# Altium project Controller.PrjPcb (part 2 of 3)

## Sheet Drivers - 34P.SchDoc: DRIVERS (34P) - 60KW GM4 DAB CONTROL
size 431 x 279 mm; Date: 02/2025; DocumentNumber: CRD60DD12N-GMB-CONTROL; Revision: 2.0; SheetNumber: 4; SheetTotal: 12; SheetSize: B
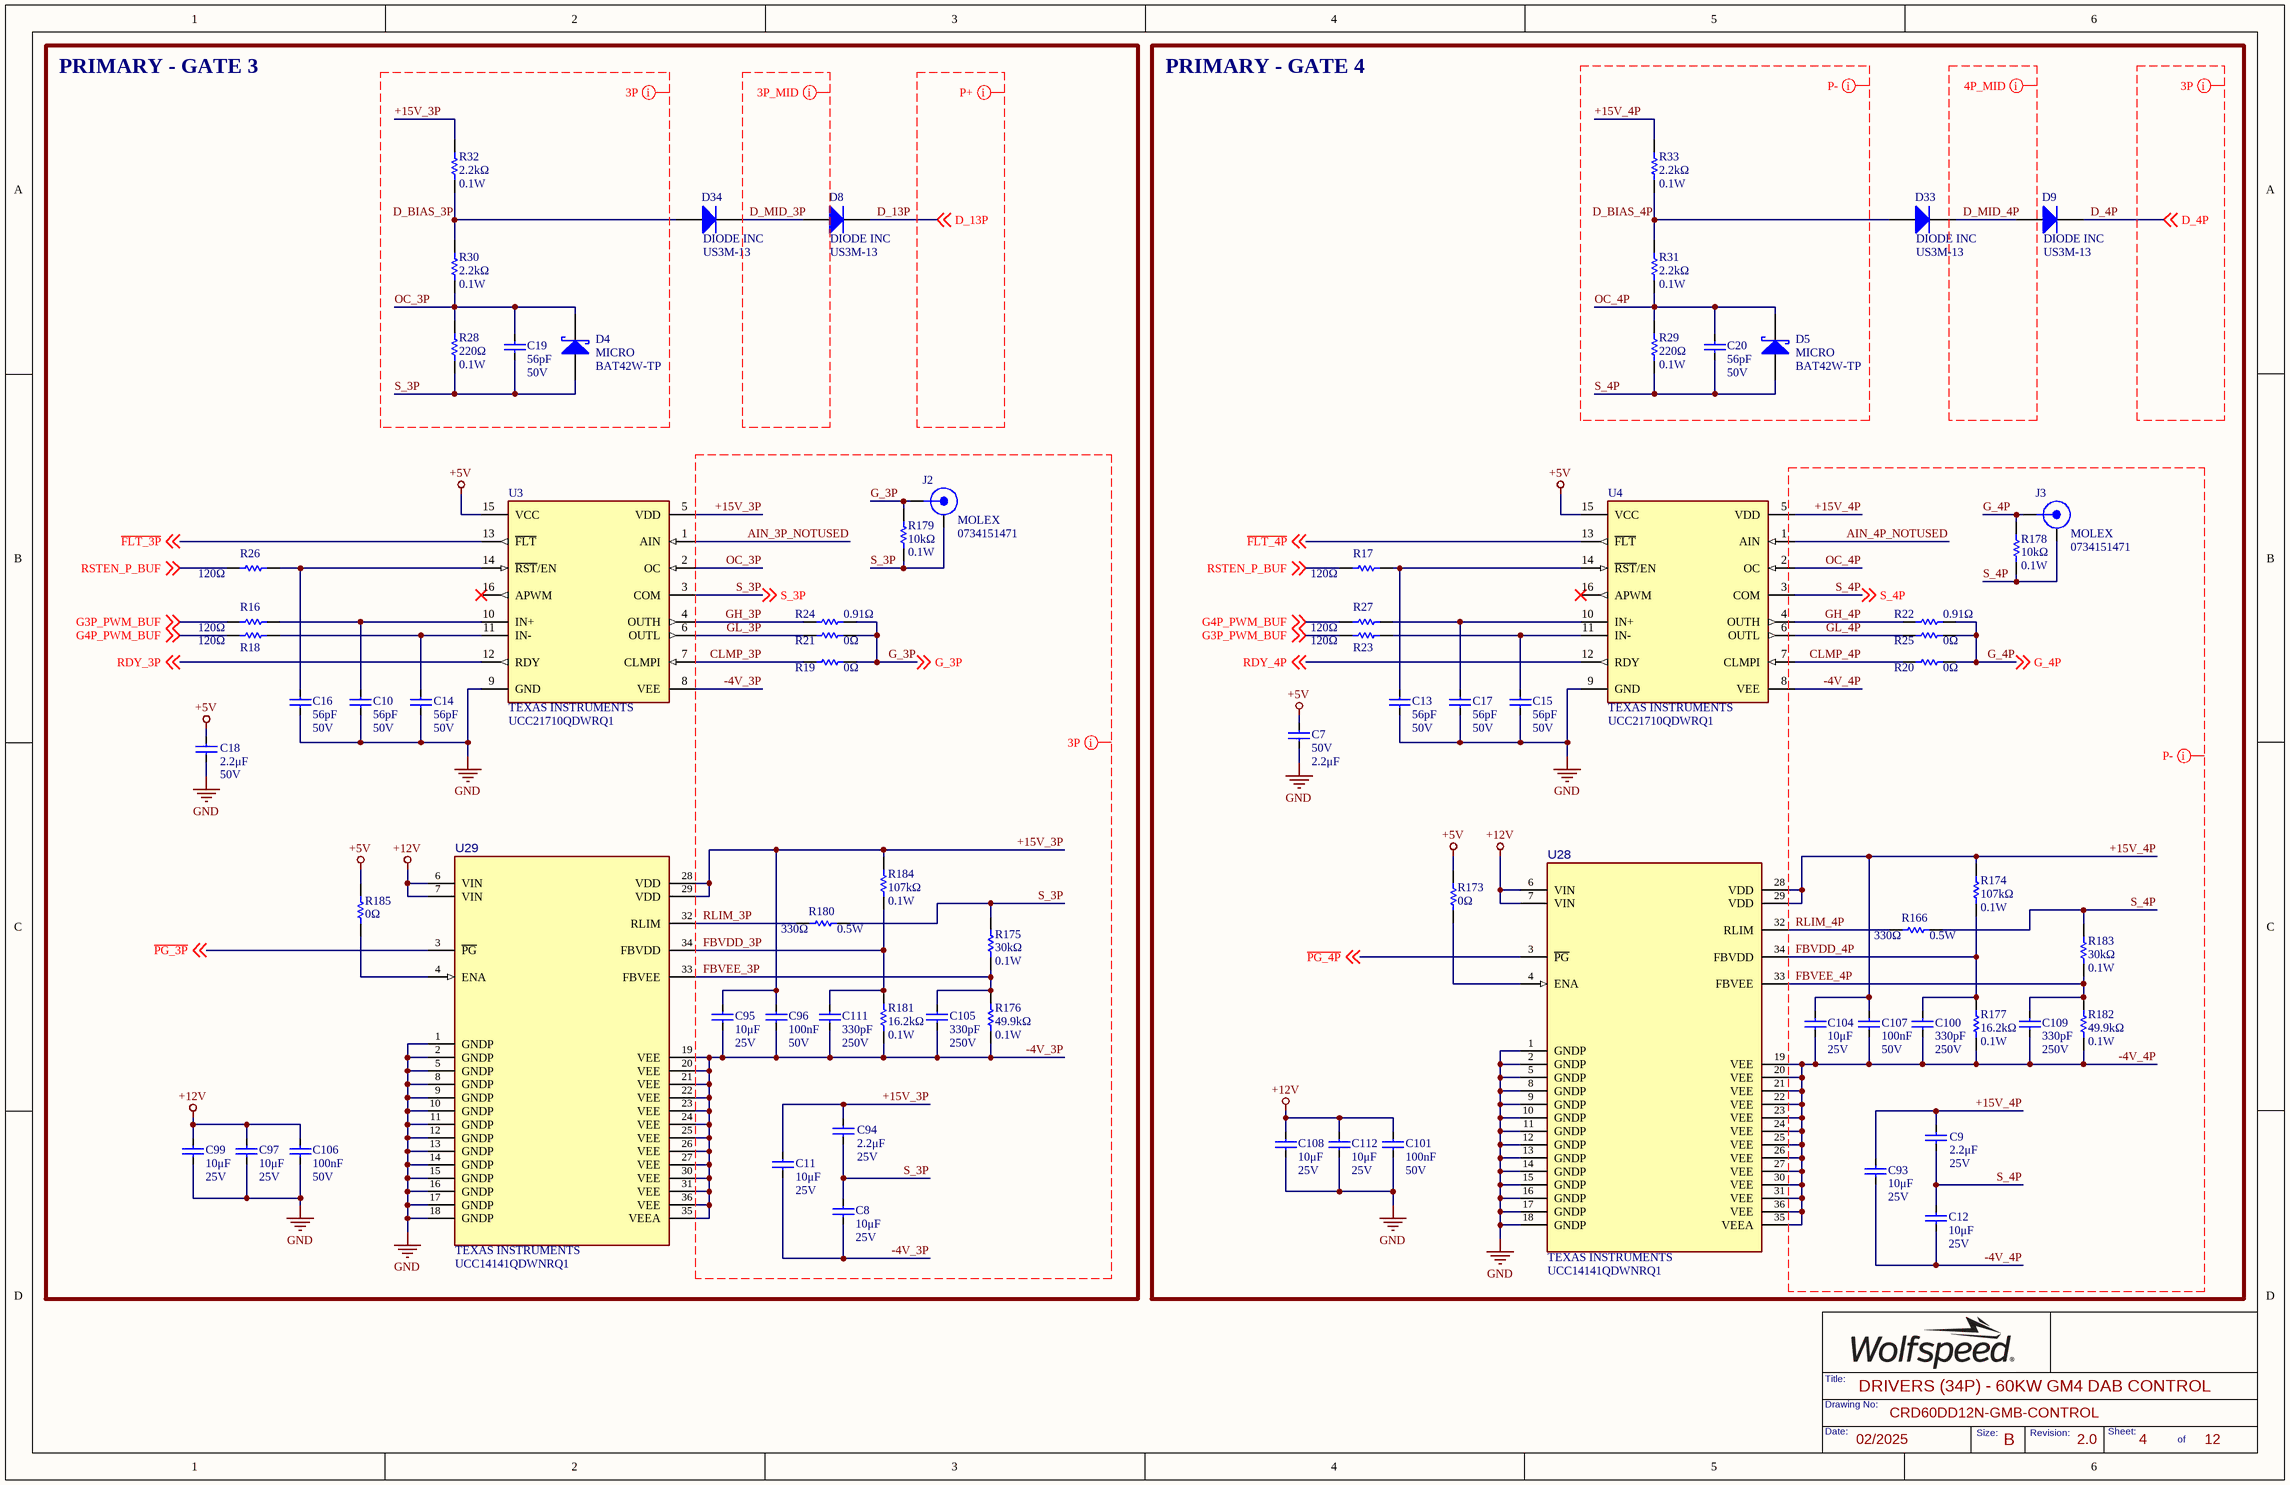
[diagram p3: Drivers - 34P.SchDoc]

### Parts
C7  Voltage Rating: 50V  Capacitance: 2.2μF  [FP-C0603C-CF-IPC_B]  (hidden comment: GRT188R61H225ME13D)
C8  value 10μF  Voltage Rating: 25V  [FP-CL31-IPC_C]  (hidden comment: CL31B106KAHSFNE)
C9  Voltage Rating: 25V  Capacitance: 2.2μF  [FP-CL31-IPC_C]  (hidden comment: 12063C225K4T2A)
C10  Capacitance: 56pF  Voltage Rating: 50V  [FP-C0603C-CF-IPC_B]  (hidden comment: CL10C560JB8NNNC)
C11  value 10μF  Voltage Rating: 25V  [FP-CL31-IPC_C]  (hidden comment: CL31B106KAHSFNE)
C12  value 10μF  Voltage Rating: 25V  [FP-CL31-IPC_C]  (hidden comment: CL31B106KAHSFNE)
C13  Capacitance: 56pF  Voltage Rating: 50V  [FP-C0603C-CF-IPC_B]  (hidden comment: CL10C560JB8NNNC)
C14  Capacitance: 56pF  Voltage Rating: 50V  [FP-C0603C-CF-IPC_B]  (hidden comment: CL10C560JB8NNNC)
C15  Capacitance: 56pF  Voltage Rating: 50V  [FP-C0603C-CF-IPC_B]  (hidden comment: CL10C560JB8NNNC)
C16  Capacitance: 56pF  Voltage Rating: 50V  [FP-C0603C-CF-IPC_B]  (hidden comment: CL10C560JB8NNNC)
C17  Capacitance: 56pF  Voltage Rating: 50V  [FP-C0603C-CF-IPC_B]  (hidden comment: CL10C560JB8NNNC)
C18  Voltage Rating: 50V  Capacitance: 2.2μF  [FP-C0603C-CF-IPC_B]  (hidden comment: GRT188R61H225ME13D)
C19  Capacitance: 56pF  Voltage Rating: 50V  [FP-C0603C-CF-IPC_B]  (hidden comment: CL10C560JB8NNNC)
C20  Capacitance: 56pF  Voltage Rating: 50V  [FP-C0603C-CF-IPC_B]  (hidden comment: CL10C560JB8NNNC)
C93  value 10μF  Voltage Rating: 25V  [FP-CL31-IPC_C]  (hidden comment: CL31B106KAHSFNE)
C94  Voltage Rating: 25V  Capacitance: 2.2μF  [FP-CL31-IPC_C]  (hidden comment: 12063C225K4T2A)
C95  value 10μF  Voltage Rating: 25V  [FP-CL31-IPC_C]  (hidden comment: CL31B106KAHSFNE)
C96  value 100nF  Voltage: 50V  [FP-C0603C-CF-IPC_B]  (hidden comment: CGA3E2X7R1H104K080AA)
C97  value 10μF  Voltage Rating: 25V  [FP-CL31-IPC_C]  (hidden comment: CL31B106KAHSFNE)
C99  value 10μF  Voltage Rating: 25V  [FP-CL31-IPC_C]  (hidden comment: CL31B106KAHSFNE)
C100  value 330pF  Voltage Rating: 250V  [FP-C0603C-CF-IPC_B]  (hidden comment: C0603C331JAGAC7867)
C101  value 100nF  Voltage: 50V  [FP-C0603C-CF-IPC_B]  (hidden comment: CGA3E2X7R1H104K080AA)
C104  value 10μF  Voltage Rating: 25V  [FP-CL31-IPC_C]  (hidden comment: CL31B106KAHSFNE)
C105  value 330pF  Voltage Rating: 250V  [FP-C0603C-CF-IPC_B]  (hidden comment: C0603C331JAGAC7867)
C106  value 100nF  Voltage: 50V  [FP-C0603C-CF-IPC_B]  (hidden comment: CGA3E2X7R1H104K080AA)
C107  value 100nF  Voltage: 50V  [FP-C0603C-CF-IPC_B]  (hidden comment: CGA3E2X7R1H104K080AA)
C108  value 10μF  Voltage Rating: 25V  [FP-CL31-IPC_C]  (hidden comment: CL31B106KAHSFNE)
C109  value 330pF  Voltage Rating: 250V  [FP-C0603C-CF-IPC_B]  (hidden comment: C0603C331JAGAC7867)
C111  value 330pF  Voltage Rating: 250V  [FP-C0603C-CF-IPC_B]  (hidden comment: C0603C331JAGAC7867)
C112  value 10μF  Voltage Rating: 25V  [FP-CL31-IPC_C]  (hidden comment: CL31B106KAHSFNE)
D4  Manufacturer: MICRO  [SOD3716X135N]  (hidden comment: BAT42W-TP)
D5  Manufacturer: MICRO  [SOD3716X135N]  (hidden comment: BAT42W-TP)
D8  Manufacturer: DIODE INC  [DIOM6959X25N]  (hidden comment: US3M-13)
D9  Manufacturer: DIODE INC  [DIOM6959X25N]  (hidden comment: US3M-13)
D33  Manufacturer: DIODE INC  [DIOM6959X25N]  (hidden comment: US3M-13)
D34  Manufacturer: DIODE INC  [DIOM6959X25N]  (hidden comment: US3M-13)
J2  0734151471  Manufacturer Print: MOLEX  [FP-73415-1471-MFG]
J3  0734151471  Manufacturer Print: MOLEX  [FP-73415-1471-MFG]
R16  value 120Ω  [FP-MCR03-IPC_B]  (hidden comment: RC0603JR-07120RL)
R17  value 120Ω  [FP-MCR03-IPC_B]  (hidden comment: RC0603JR-07120RL)
R18  value 120Ω  [FP-MCR03-IPC_B]  (hidden comment: RC0603JR-07120RL)
R19  Resistance: 0Ω  [FP-MCR03-IPC_B]  (hidden comment: CRCW06030000Z0EB)
R20  Resistance: 0Ω  [FP-MCR03-IPC_B]  (hidden comment: CRCW06030000Z0EB)
R21  value 0Ω  [RESC3125X70X40NL20T20]  (hidden comment: CRCW12100000Z0EAHP)
R22  value 0.91Ω  [RESC3125X70X40NL20T20]  (hidden comment: RCWE1210R910FKEA)
R23  value 120Ω  [FP-MCR03-IPC_B]  (hidden comment: RC0603JR-07120RL)
R24  value 0.91Ω  [RESC3125X70X40NL20T20]  (hidden comment: RCWE1210R910FKEA)
R25  value 0Ω  [RESC3125X70X40NL20T20]  (hidden comment: CRCW12100000Z0EAHP)
R26  value 120Ω  [FP-MCR03-IPC_B]  (hidden comment: RC0603JR-07120RL)
R27  value 120Ω  [FP-MCR03-IPC_B]  (hidden comment: RC0603JR-07120RL)
R28  Resistance: 220Ω  Power Rating: 0.1W  [FP-MCR03-IPC_B]  (hidden comment: RT0603FRE07220RL)
R29  Resistance: 220Ω  Power Rating: 0.1W  [FP-MCR03-IPC_B]  (hidden comment: RT0603FRE07220RL)
R30  value 2.2kΩ  Power: 0.1W  [FP-MCR03-IPC_B]  (hidden comment: RC0603FR-102K2L)
R31  value 2.2kΩ  Power: 0.1W  [FP-MCR03-IPC_B]  (hidden comment: RC0603FR-102K2L)
R32  value 2.2kΩ  Power: 0.1W  [FP-MCR03-IPC_B]  (hidden comment: RC0603FR-102K2L)
R33  value 2.2kΩ  Power: 0.1W  [FP-MCR03-IPC_B]  (hidden comment: RC0603FR-102K2L)
R166  value 330Ω  Power: 0.5W  [RESC3125X70X40NL20T20]  (hidden comment: RC1210JR-07330RL)
R173  Resistance: 0Ω  [FP-MCR03-IPC_B]  (hidden comment: CRCW06030000Z0EB)
R174  value 107kΩ  Power Rating: 0.1W  [FP-MCR03-IPC_B]  (hidden comment: RT0603BRD07107KL)
R175  value 30kΩ  Power Rating: 0.1W  [FP-MCR03-IPC_B]  (hidden comment: RT0603DRE0730KL)
R176  value 49.9kΩ  Power Rating: 0.1W  [FP-MCR03-IPC_B]  (hidden comment: RT0603FRE0749K9L)
R177  value 16.2kΩ  Power Rating: 0.1W  [FP-MCR03-IPC_B]  (hidden comment: RT0603BRD0716K2L)
R178  Resistance: 10kΩ  Max Power Dissipation: 0.1W  [FP-MCR03-IPC_B]  (hidden comment: ERJ3EKF1002V)
R179  Resistance: 10kΩ  Max Power Dissipation: 0.1W  [FP-MCR03-IPC_B]  (hidden comment: ERJ3EKF1002V)
R180  value 330Ω  Power: 0.5W  [RESC3125X70X40NL20T20]  (hidden comment: RC1210JR-07330RL)
R181  value 16.2kΩ  Power Rating: 0.1W  [FP-MCR03-IPC_B]  (hidden comment: RT0603BRD0716K2L)
R182  value 49.9kΩ  Power Rating: 0.1W  [FP-MCR03-IPC_B]  (hidden comment: RT0603FRE0749K9L)
R183  value 30kΩ  Power Rating: 0.1W  [FP-MCR03-IPC_B]  (hidden comment: RT0603DRE0730KL)
R184  value 107kΩ  Power Rating: 0.1W  [FP-MCR03-IPC_B]  (hidden comment: RT0603BRD07107KL)
R185  Resistance: 0Ω  [FP-MCR03-IPC_B]  (hidden comment: CRCW06030000Z0EB)
U3  UCC21710QDWRQ1  Manufacturer: TEXAS INSTRUMENTS  [FP-DW0016B-IPC_B]
U4  UCC21710QDWRQ1  Manufacturer: TEXAS INSTRUMENTS  [FP-DW0016B-IPC_B]
U28  Manufacturer: TEXAS INSTRUMENTS  [DWN0036-IPC-MFG]  (hidden comment: UCC14141QDWNRQ1)
U29  Manufacturer: TEXAS INSTRUMENTS  [DWN0036-IPC-MFG]  (hidden comment: UCC14141QDWNRQ1)

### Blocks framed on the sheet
PRIMARY - GATE 3: C8 C10 C11 C14 C16 C18 C19 C94-C97 C99 C105 C106 C111 D4 D8 D34 J2 R16 R18 R19 R21 R24 R26 R28 R30 R32 R175 R176 R179-R181 R184 R185 U3 U29
PRIMARY - GATE 4: C7 C9 C12 C13 C15 C17 C20 C93 C100 C101 C104 C107-C109 C112 D5 D9 D33 J3 R17 R20 R22 R23 R25 R27 R29 R31 R33 R166 R173 R174 R177 R178 R182 R183 U4 U28

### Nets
+5V: C7.1 C18.1 R173.2 R185.2 U3.15(VCC) U4.15(VCC)
+12V: C97.1 C99.1 C101.1 C106.1 C108.1 C112.1 U28.6(VIN) U28.7(VIN) U29.6(VIN) U29.7(VIN)
GND: C7.2 C10.2 C13.2 C14.2 C15.2 C16.2 C17.2 C18.2 C97.2 C99.2 C101.2 C106.2 C108.2 C112.2 U3.9(GND) U4.9(GND) U28.1(GNDP) U28.2(GNDP) U28.5(GNDP) U28.8(GNDP) U28.9(GNDP) U28.10(GNDP) U28.11(GNDP) U28.12(GNDP) U28.13(GNDP) U28.14(GNDP) U28.15(GNDP) U28.16(GNDP) U28.17(GNDP) U28.18(GNDP) U29.1(GNDP) U29.2(GNDP) U29.5(GNDP) U29.8(GNDP) U29.9(GNDP) U29.10(GNDP) U29.11(GNDP) U29.12(GNDP) U29.13(GNDP) U29.14(GNDP) U29.15(GNDP) U29.16(GNDP) U29.17(GNDP) U29.18(GNDP)
+15V_3P: C11.1 C94.1 C95.1 C96.1 R32.2 R184.2 U3.5(VDD) U29.28(VDD) U29.29(VDD)
+15V_4P: C9.1 C93.1 C104.1 C107.1 R33.2 R174.2 U4.5(VDD) U28.28(VDD) U28.29(VDD)
-4V_3P: C8.2 C11.2 C95.2 C96.2 C105.2 C111.2 R176.1 R181.1 U3.8(VEE) U29.19(VEE) U29.20(VEE) U29.21(VEE) U29.22(VEE) U29.23(VEE) U29.24(VEE) U29.25(VEE) U29.26(VEE) U29.27(VEE) U29.30(VEE) U29.31(VEE) U29.35(VEEA) U29.36(VEE)
-4V_4P: C12.2 C93.2 C100.2 C104.2 C107.2 C109.2 R177.1 R182.1 U4.8(VEE) U28.19(VEE) U28.20(VEE) U28.21(VEE) U28.22(VEE) U28.23(VEE) U28.24(VEE) U28.25(VEE) U28.26(VEE) U28.27(VEE) U28.30(VEE) U28.31(VEE) U28.35(VEEA) U28.36(VEE)
AIN_3P_NOTUSED: U3.1(AIN)
AIN_4P_NOTUSED: U4.1(AIN)
CLMP_3P: R19.1 U3.7(CLMPI)
CLMP_4P: R20.1 U4.7(CLMPI)
D_4P: D9.1(K) ; off-sheet D_4P
D_13P: D8.1(K) ; off-sheet D_13P
D_BIAS_3P: D34.2(A) R30.2 R32.1
D_BIAS_4P: D33.2(A) R31.2 R33.1
D_MID_3P: D8.2(A) D34.1(K)
D_MID_4P: D9.2(A) D33.1(K)
~{FLT_3P}: U3.13(~{FLT}) ; off-sheet ~{FLT_3P}
~{FLT_4P}: U4.13(~{FLT}) ; off-sheet ~{FLT_4P}
FBVDD_3P: C111.1 R181.2 R184.1 U29.34(FBVDD)
FBVDD_4P: C100.1 R174.1 R177.2 U28.34(FBVDD)
FBVEE_3P: C105.1 R175.1 R176.2 U29.33(FBVEE)
FBVEE_4P: C109.1 R182.2 R183.1 U28.33(FBVEE)
G3P_PWM_BUF: R16.1 R23.1 ; off-sheet G3P_PWM_BUF
G4P_PWM_BUF: R18.1 R27.1 ; off-sheet G4P_PWM_BUF
G_3P: J2.1(CENTER) R19.2 R21.2 R24.2 R179.2 ; off-sheet G_3P
G_4P: J3.1(CENTER) R20.2 R22.2 R25.2 R178.2 ; off-sheet G_4P
GH_3P: R24.1 U3.4(OUTH)
GH_4P: R22.1 U4.4(OUTH)
GL_3P: R21.1 U3.6(OUTL)
GL_4P: R25.1 U4.6(OUTL)
OC_3P: C19.1 D4.1(K) R28.2 R30.1 U3.2(OC)
OC_4P: C20.1 D5.1(K) R29.2 R31.1 U4.2(OC)
~{PG_3P}: U29.3(~{PG}) ; off-sheet ~{PG_3P}
~{PG_4P}: U28.3(~{PG}) ; off-sheet ~{PG_4P}
RDY_3P: U3.12(RDY) ; off-sheet RDY_3P
RDY_4P: U4.12(RDY) ; off-sheet RDY_4P
RLIM_3P: R180.1 U29.32(RLIM)
RLIM_4P: R166.1 U28.32(RLIM)
RSTEN_P_BUF: R17.1 R26.1 ; off-sheet RSTEN_P_BUF
S_3P: C8.1 C19.2 C94.2 D4.2(A) J2.2,3,4,5(SHIELD) R28.1 R175.2 R179.1 R180.2 U3.3(COM) ; off-sheet S_3P
S_4P: C9.2 C12.1 C20.2 D5.2(A) J3.2,3,4,5(SHIELD) R29.1 R166.2 R178.1 R183.2 U4.3(COM) ; off-sheet S_4P
NetC10_1: C10.1 R16.2 U3.10(IN+)
NetC13_1: C13.1 R17.2 U4.14(~{RST}/EN)
NetC14_1: C14.1 R18.2 U3.11(IN-)
NetC15_1: C15.1 R23.2 U4.11(IN-)
NetC16_1: C16.1 R26.2 U3.14(~{RST}/EN)
NetC17_1: C17.1 R27.2 U4.10(IN+)
NetR173_1: R173.1 U28.4(ENA)
NetR185_1: R185.1 U29.4(ENA)

Not connected (* = marked no-connect by the designer): U3 16(APWM)*; U4 16(APWM)*

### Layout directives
net class P-_CLASS: +15V_4P, -4V_4P, AIN_4P_NOTUSED, CLMP_4P, D_BIAS_4P, FBVDD_4P, FBVEE_4P, G_4P, GH_4P, GL_4P, OC_4P, RLIM_4P, S_4P
net class 3P_CLASS: +15V_3P, -4V_3P, AIN_3P_NOTUSED, CLMP_3P, D_4P, D_BIAS_3P, FBVDD_3P, FBVEE_3P, G_3P, GH_3P, GL_3P, OC_3P, RLIM_3P, S_3P
net class P+_CLASS: D_13P
net class 3PMID_CLASS: D_MID_3P
net class 4PMID_CLASS: D_MID_4P

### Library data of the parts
C7 C18 = GRT188R61H225ME13D: CAP CER 2.2UF 50V X5R 0603; Manufacturer: MURATA; Tolerance: 20%; Value: 2.2μF
C8 C11 C12 C93 C95 C97 C99 C104 C108 C112 = CL31B106KAHSFNE: CAP CER 10UF 25V X7R 1206; Manufacturer: SAMSUNG; Tolerance: 10%
C9 C94 = 12063C225K4T2A: CAP CER 2.2UF 25V X7R 1206; Manufacturer: KYOCERA; Tolerance: 10%; Value: 2.2μF
C10 C13-C17 C19 C20 = CL10C560JB8NNNC: CAP CER 56PF 50V C0G/NP0 0603; Manufacturer: SAMSUNG; Material: Ceramic; Tolerance: 5%; Dielectric: C0G; Temperature Coefficient: 30ppm/°C
C96 C101 C106 C107 = CGA3E2X7R1H104K080AA: CAP CER 0.1UF 50V X7R 0603; Manufacturer: TDK; Material: 4241ConductorMaterial; Tolerance: 10%
C100 C105 C109 C111 = C0603C331JAGAC7867: CAP CER 330PF 250V C0G/NP0 0603; Manufacturer: KEMET; Material: Ceramic; Temperature Coefficient: 30ppm/°C; Tolerance: 0.05; Automotive Grade: Grade 1; Temperature Characteristic: C0G
D4 D5 = BAT42W-TP: DIODE SCHOTTKY 30V 200MA SOD123
D8 D9 D33 D34 = CMP-004-00052-3: DIODE GEN PURP 1KV 3A SMC
J2 J3 = 0734151471: CONN MMCX JACK STR 50 OHM PCB; Body Material: Brass; Body Plating: Gold; Impedance: 50R; Connector Type: PCB,MMCX,Coaxial; Max Frequency: 6GHz; Gender: Female
R16-R18 R23 R26 R27 = RC0603JR-07120RL: RES SMD 120 OHM 5% 1/10W 0603; Manufacturer: YAGEO; Voltage Rating (DC): 50V; Temperature Coefficient: 100ppm/°C; Power Rating: 100mW
R19 R20 R173 R185 = CRCW06030000Z0EB: RES SMD 0 OHM JUMPER 1/10W 0603; Manufacturer: VISHAY DALE; Max Power Dissipation: 100mW; Voltage Rating: 75V; Tolerance: 1%; Temperature Coefficient: 100ppm/°C; Value: 0Ω
R21 R25 = CRCW12100000Z0EAHP: RES SMD 0 OHM JUMPER 3/4W 1210; Manufacturer: VISHAY DALE; Max Power Dissipation: 750mW
R22 R24 = CMP-2005-02198-1: RES 0.91 OHM 1% 1W 1210; Manufacturer: VISHAY DALE
R28 R29 = RT0603FRE07220RL: RES SMD 220 OHM 1% 1/10W 0603; Manufacturer: YAGEO; Temperature Coefficient: 50 ppm/°C; Tolerance: 0.01; Voltage Rating: 75V; Value: 220Ω
R30-R33 = RC0603FR-102K2L: RES 2.2K OHM 1% 1/10W 0603; Manufacturer: YAGEO
R166 R180 = RC1210JR-07330RL: RES 330 OHM 5% 1/2W 1210; Manufacturer: YAGEO
R174 R184 = RT0603BRD07107KL: RES SMD 107K OHM 0.1% 1/10W 0603; Manufacturer: YAGEO; Temperature Coefficient: 25 ppm/°C; Tolerance: 0.001; Voltage Rating: 75V
R175 R183 = RT0603DRE0730KL: RES SMD 30K OHM 0.5% 1/10W 0603; Manufacturer: YAGEO; Temperature Coefficient: 50 ppm/°C; Tolerance: 0.005; Voltage Rating: 75V
R176 R182 = RT0603FRE0749K9L: RES SMD 49.9K OHM 1% 1/10W 0603; Manufacturer: YAGEO; Temperature Coefficient: 50ppm/°C; Max Power Dissipation: 100mW; Voltage Rating: 75V; Voltage Rating (DC): 50V
R177 R181 = RT0603BRD0716K2L: RES SMD 16.2K OHM 0.1% 1/10W; Manufacturer: YAGEO; Tolerance: 0.001; Voltage Rating: 75V; Temperature Coefficient: 25 ppm/°C
R178 R179 = ERJ3EKF1002V: RES SMD 10K OHM 1% 1/10W 0603; Manufacturer: PANASONIC; Manufacturer Part Number: ERJ-3EKF1002V; Temperature Coefficient: 100ppm/°C; Power Rating: 100mW; Voltage Rating: 75V; Value: 10kΩ
U3 U4 = CMP-00024-00019-13: DGTL ISO 5.7KV 1CH GT DVR 16SOIC
U28 U29 = UCC14141QDWNRQ1: DUAL DC DC CONVERTER 1.5W; Part Number: UCC14240DWNQ1; Max Supply Voltage: 27V; Standoff Height: 0.1mm; SizeZ_mm: 3.55mm; AEC Qualified: Yes; Output Voltage: 18-25/2.5-25V; TaMin_C: -40°C; CompType: IC; TJmax_C: +150°C; Min Supply Voltage: 21V; AEC Grade: Grade 1; Number Of Outputs: 2; Output Type: AdjustableProgrammable; TaMax_C: +125°C; AEC Category: Q200

## Sheet Drivers - 12S.SchDoc: DRIVERS (12S) - 60KW GM4 DAB CONTROL
size 431 x 279 mm; Date: 02/2025; DocumentNumber: CRD60DD12N-GMB-CONTROL; Revision: 2.0; SheetNumber: 5; SheetTotal: 12; SheetSize: B
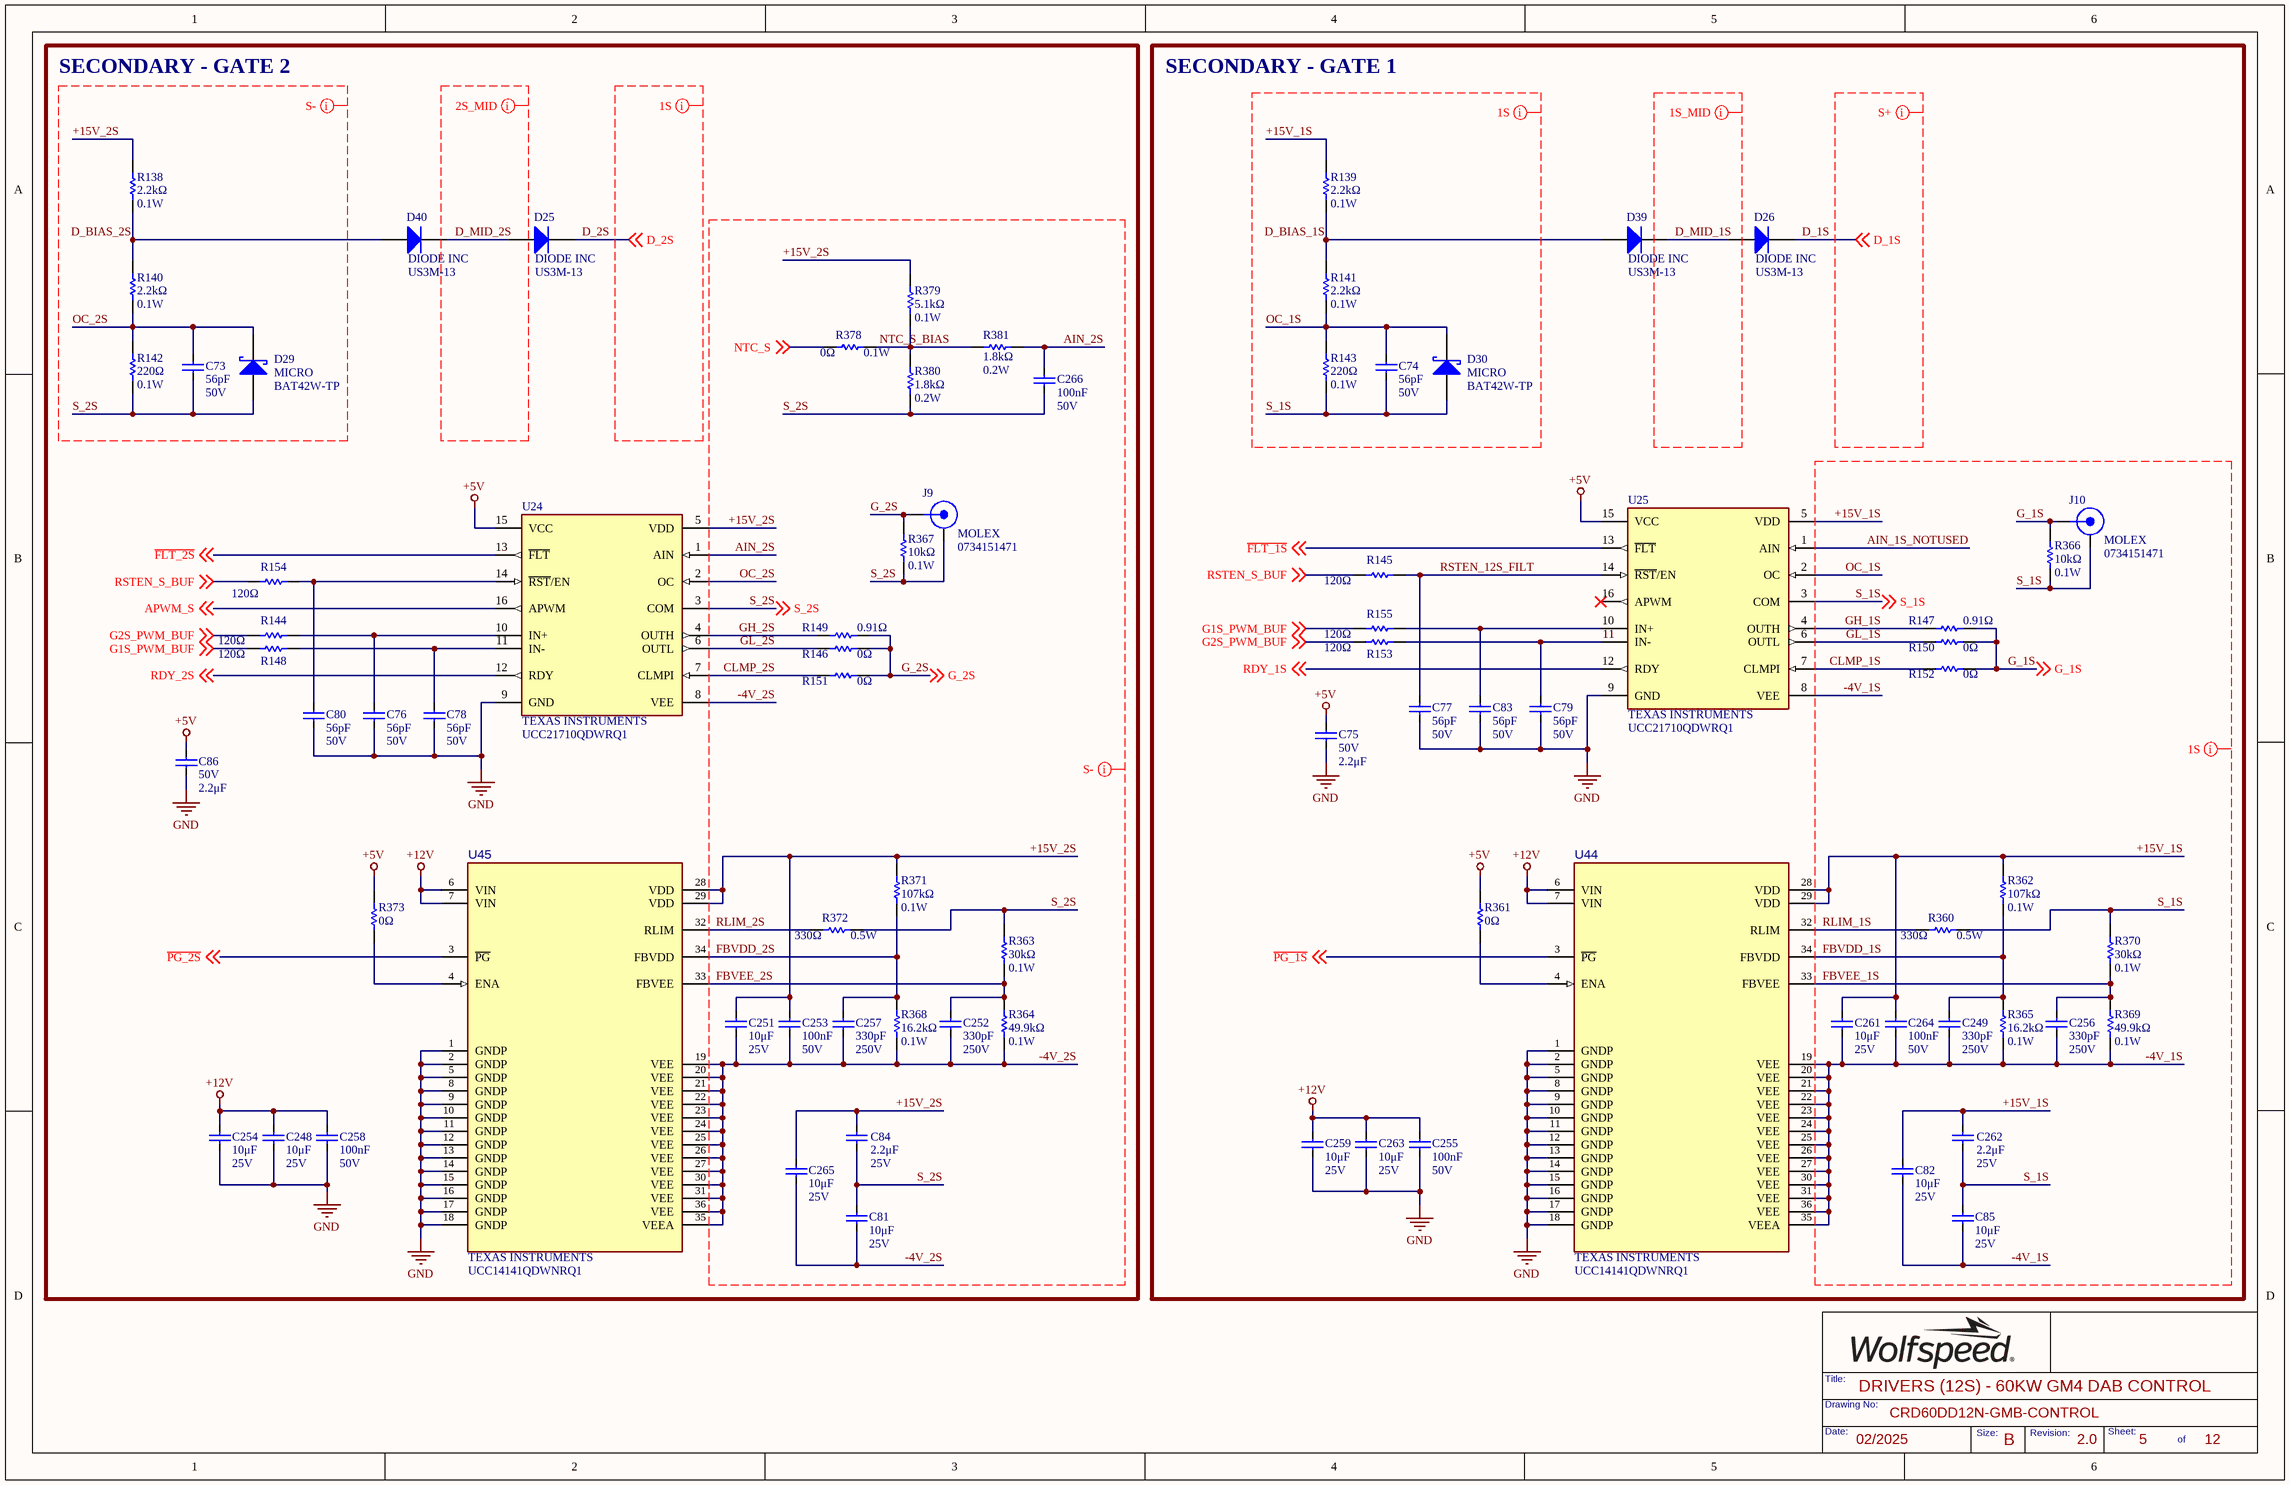
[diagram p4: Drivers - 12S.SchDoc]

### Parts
C73  Capacitance: 56pF  Voltage Rating: 50V  [FP-C0603C-CF-IPC_B]  (hidden comment: CL10C560JB8NNNC)
C74  Capacitance: 56pF  Voltage Rating: 50V  [FP-C0603C-CF-IPC_B]  (hidden comment: CL10C560JB8NNNC)
C75  Voltage Rating: 50V  Capacitance: 2.2μF  [FP-C0603C-CF-IPC_B]  (hidden comment: GRT188R61H225ME13D)
C76  Capacitance: 56pF  Voltage Rating: 50V  [FP-C0603C-CF-IPC_B]  (hidden comment: CL10C560JB8NNNC)
C77  Capacitance: 56pF  Voltage Rating: 50V  [FP-C0603C-CF-IPC_B]  (hidden comment: CL10C560JB8NNNC)
C78  Capacitance: 56pF  Voltage Rating: 50V  [FP-C0603C-CF-IPC_B]  (hidden comment: CL10C560JB8NNNC)
C79  Capacitance: 56pF  Voltage Rating: 50V  [FP-C0603C-CF-IPC_B]  (hidden comment: CL10C560JB8NNNC)
C80  Capacitance: 56pF  Voltage Rating: 50V  [FP-C0603C-CF-IPC_B]  (hidden comment: CL10C560JB8NNNC)
C81  value 10μF  Voltage Rating: 25V  [FP-CL31-IPC_C]  (hidden comment: CL31B106KAHSFNE)
C82  value 10μF  Voltage Rating: 25V  [FP-CL31-IPC_C]  (hidden comment: CL31B106KAHSFNE)
C83  Capacitance: 56pF  Voltage Rating: 50V  [FP-C0603C-CF-IPC_B]  (hidden comment: CL10C560JB8NNNC)
C84  Voltage Rating: 25V  Capacitance: 2.2μF  [FP-CL31-IPC_C]  (hidden comment: 12063C225K4T2A)
C85  value 10μF  Voltage Rating: 25V  [FP-CL31-IPC_C]  (hidden comment: CL31B106KAHSFNE)
C86  Voltage Rating: 50V  Capacitance: 2.2μF  [FP-C0603C-CF-IPC_B]  (hidden comment: GRT188R61H225ME13D)
C248  value 10μF  Voltage Rating: 25V  [FP-CL31-IPC_C]  (hidden comment: CL31B106KAHSFNE)
C249  value 330pF  Voltage Rating: 250V  [FP-C0603C-CF-IPC_B]  (hidden comment: C0603C331JAGAC7867)
C251  value 10μF  Voltage Rating: 25V  [FP-CL31-IPC_C]  (hidden comment: CL31B106KAHSFNE)
C252  value 330pF  Voltage Rating: 250V  [FP-C0603C-CF-IPC_B]  (hidden comment: C0603C331JAGAC7867)
C253  value 100nF  Voltage: 50V  [FP-C0603C-CF-IPC_B]  (hidden comment: CGA3E2X7R1H104K080AA)
C254  value 10μF  Voltage Rating: 25V  [FP-CL31-IPC_C]  (hidden comment: CL31B106KAHSFNE)
C255  value 100nF  Voltage: 50V  [FP-C0603C-CF-IPC_B]  (hidden comment: CGA3E2X7R1H104K080AA)
C256  value 330pF  Voltage Rating: 250V  [FP-C0603C-CF-IPC_B]  (hidden comment: C0603C331JAGAC7867)
C257  value 330pF  Voltage Rating: 250V  [FP-C0603C-CF-IPC_B]  (hidden comment: C0603C331JAGAC7867)
C258  value 100nF  Voltage: 50V  [FP-C0603C-CF-IPC_B]  (hidden comment: CGA3E2X7R1H104K080AA)
C259  value 10μF  Voltage Rating: 25V  [FP-CL31-IPC_C]  (hidden comment: CL31B106KAHSFNE)
C261  value 10μF  Voltage Rating: 25V  [FP-CL31-IPC_C]  (hidden comment: CL31B106KAHSFNE)
C262  Voltage Rating: 25V  Capacitance: 2.2μF  [FP-CL31-IPC_C]  (hidden comment: 12063C225K4T2A)
C263  value 10μF  Voltage Rating: 25V  [FP-CL31-IPC_C]  (hidden comment: CL31B106KAHSFNE)
C264  value 100nF  Voltage: 50V  [FP-C0603C-CF-IPC_B]  (hidden comment: CGA3E2X7R1H104K080AA)
C265  value 10μF  Voltage Rating: 25V  [FP-CL31-IPC_C]  (hidden comment: CL31B106KAHSFNE)
C266  value 100nF  Voltage: 50V  [FP-C0603C-CF-IPC_B]  (hidden comment: CGA3E2X7R1H104K080AA)
D25  Manufacturer: DIODE INC  [DIOM6959X25N]  (hidden comment: US3M-13)
D26  Manufacturer: DIODE INC  [DIOM6959X25N]  (hidden comment: US3M-13)
D29  Manufacturer: MICRO  [SOD3716X135N]  (hidden comment: BAT42W-TP)
D30  Manufacturer: MICRO  [SOD3716X135N]  (hidden comment: BAT42W-TP)
D39  Manufacturer: DIODE INC  [DIOM6959X25N]  (hidden comment: US3M-13)
D40  Manufacturer: DIODE INC  [DIOM6959X25N]  (hidden comment: US3M-13)
J9  0734151471  Manufacturer Print: MOLEX  [FP-73415-1471-MFG]
J10  0734151471  Manufacturer Print: MOLEX  [FP-73415-1471-MFG]
R138  value 2.2kΩ  Power: 0.1W  [FP-MCR03-IPC_B]  (hidden comment: RC0603FR-102K2L)
R139  value 2.2kΩ  Power: 0.1W  [FP-MCR03-IPC_B]  (hidden comment: RC0603FR-102K2L)
R140  value 2.2kΩ  Power: 0.1W  [FP-MCR03-IPC_B]  (hidden comment: RC0603FR-102K2L)
R141  value 2.2kΩ  Power: 0.1W  [FP-MCR03-IPC_B]  (hidden comment: RC0603FR-102K2L)
R142  Resistance: 220Ω  Power Rating: 0.1W  [FP-MCR03-IPC_B]  (hidden comment: RT0603FRE07220RL)
R143  Resistance: 220Ω  Power Rating: 0.1W  [FP-MCR03-IPC_B]  (hidden comment: RT0603FRE07220RL)
R144  value 120Ω  [FP-MCR03-IPC_B]  (hidden comment: RC0603JR-07120RL)
R145  value 120Ω  [FP-MCR03-IPC_B]  (hidden comment: RC0603JR-07120RL)
R146  value 0Ω  [RESC3125X70X40NL20T20]  (hidden comment: CRCW12100000Z0EAHP)
R147  value 0.91Ω  [RESC3125X70X40NL20T20]  (hidden comment: RCWE1210R910FKEA)
R148  value 120Ω  [FP-MCR03-IPC_B]  (hidden comment: RC0603JR-07120RL)
R149  value 0.91Ω  [RESC3125X70X40NL20T20]  (hidden comment: RCWE1210R910FKEA)
R150  value 0Ω  [RESC3125X70X40NL20T20]  (hidden comment: CRCW12100000Z0EAHP)
R151  Resistance: 0Ω  [FP-MCR03-IPC_B]  (hidden comment: CRCW06030000Z0EB)
R152  Resistance: 0Ω  [FP-MCR03-IPC_B]  (hidden comment: CRCW06030000Z0EB)
R153  value 120Ω  [FP-MCR03-IPC_B]  (hidden comment: RC0603JR-07120RL)
R154  value 120Ω  [FP-MCR03-IPC_B]  (hidden comment: RC0603JR-07120RL)
R155  value 120Ω  [FP-MCR03-IPC_B]  (hidden comment: RC0603JR-07120RL)
R360  value 330Ω  Power: 0.5W  [RESC3125X70X40NL20T20]  (hidden comment: RC1210JR-07330RL)
R361  Resistance: 0Ω  [FP-MCR03-IPC_B]  (hidden comment: CRCW06030000Z0EB)
R362  value 107kΩ  Power Rating: 0.1W  [FP-MCR03-IPC_B]  (hidden comment: RT0603BRD07107KL)
R363  value 30kΩ  Power Rating: 0.1W  [FP-MCR03-IPC_B]  (hidden comment: RT0603DRE0730KL)
R364  value 49.9kΩ  Power Rating: 0.1W  [FP-MCR03-IPC_B]  (hidden comment: RT0603FRE0749K9L)
R365  value 16.2kΩ  Power Rating: 0.1W  [FP-MCR03-IPC_B]  (hidden comment: RT0603BRD0716K2L)
R366  Resistance: 10kΩ  Max Power Dissipation: 0.1W  [FP-MCR03-IPC_B]  (hidden comment: ERJ3EKF1002V)
R367  Resistance: 10kΩ  Max Power Dissipation: 0.1W  [FP-MCR03-IPC_B]  (hidden comment: ERJ3EKF1002V)
R368  value 16.2kΩ  Power Rating: 0.1W  [FP-MCR03-IPC_B]  (hidden comment: RT0603BRD0716K2L)
R369  value 49.9kΩ  Power Rating: 0.1W  [FP-MCR03-IPC_B]  (hidden comment: RT0603FRE0749K9L)
R370  value 30kΩ  Power Rating: 0.1W  [FP-MCR03-IPC_B]  (hidden comment: RT0603DRE0730KL)
R371  value 107kΩ  Power Rating: 0.1W  [FP-MCR03-IPC_B]  (hidden comment: RT0603BRD07107KL)
R372  value 330Ω  Power: 0.5W  [RESC3125X70X40NL20T20]  (hidden comment: RC1210JR-07330RL)
R373  Resistance: 0Ω  [FP-MCR03-IPC_B]  (hidden comment: CRCW06030000Z0EB)
R378  Resistance: 0Ω  Power Rating: 0.1W  [FP-MCR03-IPC_B]  (hidden comment: CRCW06030000Z0EB)
R379  value 5.1kΩ  Power: 0.1W  [FP-MCR03-IPC_B]  (hidden comment: RC0603FR-075K1L)
R380  Resistance: 1.8kΩ  Max Power Dissipation: 0.2W  [FP-MCR03-IPC_B]  (hidden comment: ERJ-PB3B1801V)
R381  Resistance: 1.8kΩ  Max Power Dissipation: 0.2W  [FP-MCR03-IPC_B]  (hidden comment: ERJ-PB3B1801V)
U24  UCC21710QDWRQ1  Manufacturer: TEXAS INSTRUMENTS  [FP-DW0016B-IPC_B]
U25  UCC21710QDWRQ1  Manufacturer: TEXAS INSTRUMENTS  [FP-DW0016B-IPC_B]
U44  Manufacturer: TEXAS INSTRUMENTS  [DWN0036-IPC-MFG]  (hidden comment: UCC14141QDWNRQ1)
U45  Manufacturer: TEXAS INSTRUMENTS  [DWN0036-IPC-MFG]  (hidden comment: UCC14141QDWNRQ1)

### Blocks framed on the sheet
SECONDARY - GATE 2: C73 C76 C78 C80 C81 C84 C86 C248 C251-C254 C257 C258 C265 C266 D25 D29 D40 J9 R138 R140 R142 R144 R146 R148 R149 R151 R154 R363 R364 R367 R368 R371-R373 R378-R381 U24 U45
SECONDARY - GATE 1: C74 C75 C77 C79 C82 C83 C85 C249 C255 C256 C259 C261-C264 D26 D30 D39 J10 R139 R141 R143 R145 R147 R150 R152 R153 R155 R360-R362 R365 R366 R369 R370 U25 U44

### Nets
+5V: C75.1 C86.1 R361.2 R373.2 U24.15(VCC) U25.15(VCC)
+12V: C248.1 C254.1 C255.1 C258.1 C259.1 C263.1 U44.6(VIN) U44.7(VIN) U45.6(VIN) U45.7(VIN)
GND: C75.2 C76.2 C77.2 C78.2 C79.2 C80.2 C83.2 C86.2 C248.2 C254.2 C255.2 C258.2 C259.2 C263.2 U24.9(GND) U25.9(GND) U44.1(GNDP) U44.2(GNDP) U44.5(GNDP) U44.8(GNDP) U44.9(GNDP) U44.10(GNDP) U44.11(GNDP) U44.12(GNDP) U44.13(GNDP) U44.14(GNDP) U44.15(GNDP) U44.16(GNDP) U44.17(GNDP) U44.18(GNDP) U45.1(GNDP) U45.2(GNDP) U45.5(GNDP) U45.8(GNDP) U45.9(GNDP) U45.10(GNDP) U45.11(GNDP) U45.12(GNDP) U45.13(GNDP) U45.14(GNDP) U45.15(GNDP) U45.16(GNDP) U45.17(GNDP) U45.18(GNDP)
+15V_1S: C82.1 C261.1 C262.1 C264.1 R139.2 R362.2 U25.5(VDD) U44.28(VDD) U44.29(VDD)
+15V_2S: C84.1 C251.1 C253.1 C265.1 R138.2 R371.2 R379.2 U24.5(VDD) U45.28(VDD) U45.29(VDD)
-4V_1S: C82.2 C85.2 C249.2 C256.2 C261.2 C264.2 R365.1 R369.1 U25.8(VEE) U44.19(VEE) U44.20(VEE) U44.21(VEE) U44.22(VEE) U44.23(VEE) U44.24(VEE) U44.25(VEE) U44.26(VEE) U44.27(VEE) U44.30(VEE) U44.31(VEE) U44.35(VEEA) U44.36(VEE)
-4V_2S: C81.2 C251.2 C252.2 C253.2 C257.2 C265.2 R364.1 R368.1 U24.8(VEE) U45.19(VEE) U45.20(VEE) U45.21(VEE) U45.22(VEE) U45.23(VEE) U45.24(VEE) U45.25(VEE) U45.26(VEE) U45.27(VEE) U45.30(VEE) U45.31(VEE) U45.35(VEEA) U45.36(VEE)
AIN_1S_NOTUSED: U25.1(AIN)
AIN_2S: C266.1 R381.1 U24.1(AIN)
APWM_S: U24.16(APWM) ; off-sheet APWM_S
CLMP_1S: R152.1 U25.7(CLMPI)
CLMP_2S: R151.1 U24.7(CLMPI)
D_1S: D26.1(K) ; off-sheet D_1S
D_2S: D25.1(K) ; off-sheet D_2S
D_BIAS_1S: D39.2(A) R139.1 R141.2
D_BIAS_2S: D40.2(A) R138.1 R140.2
D_MID_1S: D26.2(A) D39.1(K)
D_MID_2S: D25.2(A) D40.1(K)
~{FLT_1S}: U25.13(~{FLT}) ; off-sheet ~{FLT_1S}
~{FLT_2S}: U24.13(~{FLT}) ; off-sheet ~{FLT_2S}
FBVDD_1S: C249.1 R362.1 R365.2 U44.34(FBVDD)
FBVDD_2S: C257.1 R368.2 R371.1 U45.34(FBVDD)
FBVEE_1S: C256.1 R369.2 R370.1 U44.33(FBVEE)
FBVEE_2S: C252.1 R363.1 R364.2 U45.33(FBVEE)
G1S_PWM_BUF: R148.1 R155.1 ; off-sheet G1S_PWM_BUF
G2S_PWM_BUF: R144.1 R153.1 ; off-sheet G2S_PWM_BUF
G_1S: J10.1(CENTER) R147.2 R150.2 R152.2 R366.2 ; off-sheet G_1S
G_2S: J9.1(CENTER) R146.2 R149.2 R151.2 R367.2 ; off-sheet G_2S
GH_1S: R147.1 U25.4(OUTH)
GH_2S: R149.1 U24.4(OUTH)
GL_1S: R150.1 U25.6(OUTL)
GL_2S: R146.1 U24.6(OUTL)
NTC_S: R378.1 ; off-sheet NTC_S
NTC_S_BIAS: R378.2 R379.1 R380.2 R381.2
OC_1S: C74.1 D30.1(K) R141.1 R143.2 U25.2(OC)
OC_2S: C73.1 D29.1(K) R140.1 R142.2 U24.2(OC)
~{PG_1S}: U44.3(~{PG}) ; off-sheet ~{PG_1S}
~{PG_2S}: U45.3(~{PG}) ; off-sheet ~{PG_2S}
RDY_1S: U25.12(RDY) ; off-sheet RDY_1S
RDY_2S: U24.12(RDY) ; off-sheet RDY_2S
RLIM_1S: R360.1 U44.32(RLIM)
RLIM_2S: R372.1 U45.32(RLIM)
RSTEN_12S_FILT: C77.1 R145.2 U25.14(~{RST}/EN)
RSTEN_S_BUF: R145.1 R154.1 ; off-sheet RSTEN_S_BUF
S_1S: C74.2 C85.1 C262.2 D30.2(A) J10.2,3,4,5(SHIELD) R143.1 R360.2 R366.1 R370.2 U25.3(COM) ; off-sheet S_1S
S_2S: C73.2 C81.1 C84.2 C266.2 D29.2(A) J9.2,3,4,5(SHIELD) R142.1 R363.2 R367.1 R372.2 R380.1 U24.3(COM) ; off-sheet S_2S
NetC76_1: C76.1 R144.2 U24.10(IN+)
NetC78_1: C78.1 R148.2 U24.11(IN-)
NetC79_1: C79.1 R153.2 U25.11(IN-)
NetC80_1: C80.1 R154.2 U24.14(~{RST}/EN)
NetC83_1: C83.1 R155.2 U25.10(IN+)
NetR361_1: R361.1 U44.4(ENA)
NetR373_1: R373.1 U45.4(ENA)

Not connected (* = marked no-connect by the designer): U25 16(APWM)*

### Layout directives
net class 1S_CLASS: +15V_1S, -4V_1S, AIN_1S_NOTUSED, CLMP_1S, D_2S, D_BIAS_1S, FBVDD_1S, FBVEE_1S, G_1S, GH_1S, GL_1S, OC_1S, RLIM_1S, S_1S
net class S+_CLASS: D_1S
net class 1SMID_CLASS: D_MID_1S
net class S-_CLASS: +15V_2S, -4V_2S, AIN_2S, CLMP_2S, D_BIAS_2S, FBVDD_2S, FBVEE_2S, G_2S, GH_2S, GL_2S, NTC_S, NTC_S_BIAS, OC_2S, RLIM_2S, S_2S
net class 2SMID_CLASS: D_MID_2S

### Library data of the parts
C73 C74 C76-C80 C83 = CL10C560JB8NNNC: as C10 on sheet Drivers - 34P
C75 C86 = GRT188R61H225ME13D: as C7 on sheet Drivers - 34P
C81 C82 C85 C248 C251 C254 C259 C261 C263 C265 = CL31B106KAHSFNE: as C8 on sheet Drivers - 34P
C84 C262 = 12063C225K4T2A: as C9 on sheet Drivers - 34P
C249 C252 C256 C257 = C0603C331JAGAC7867: as C100 on sheet Drivers - 34P
C253 C255 C258 C264 C266 = CGA3E2X7R1H104K080AA: as C96 on sheet Drivers - 34P
D25 D26 D39 D40 = CMP-004-00052-3: DIODE GEN PURP 1KV 3A SMC
D29 D30 = BAT42W-TP: DIODE SCHOTTKY 30V 200MA SOD123
J9 J10 = 0734151471: as J2 on sheet Drivers - 34P
R138-R141 = RC0603FR-102K2L: as R30-R33 on sheet Drivers - 34P
R142 R143 = RT0603FRE07220RL: as R28 on sheet Drivers - 34P
R144 R145 R148 R153-R155 = RC0603JR-07120RL: as R16-R18 on sheet Drivers - 34P
R146 R150 = CRCW12100000Z0EAHP: as R21 on sheet Drivers - 34P
R147 R149 = CMP-2005-02198-1: as R22 on sheet Drivers - 34P
R151 R152 R361 R373 R378 = CRCW06030000Z0EB: as R19 on sheet Drivers - 34P
R360 R372 = RC1210JR-07330RL: as R166 on sheet Drivers - 34P
R362 R371 = RT0603BRD07107KL: as R174 on sheet Drivers - 34P
R363 R370 = RT0603DRE0730KL: as R175 on sheet Drivers - 34P
R364 R369 = RT0603FRE0749K9L: as R176 on sheet Drivers - 34P
R365 R368 = RT0603BRD0716K2L: as R177 on sheet Drivers - 34P
R366 R367 = ERJ3EKF1002V: as R178 on sheet Drivers - 34P
R379 = RC0603FR-075K1L: RES 5.1K OHM 1% 1/10W 0603; Manufacturer: YAGEO
R380 R381 = ERJ-PB3B1801V: RES SMD 1.8K OHM 0.1% 1/5W 0603; Manufacturer: PANASONIC; Temperature Coefficient: 50ppm/°C; Value: 1.8kΩ
U24 U25 = CMP-00024-00019-13: DGTL ISO 5.7KV 1CH GT DVR 16SOIC
U44 U45 = UCC14141QDWNRQ1: as U28 on sheet Drivers - 34P

## Sheet Drivers - 34S.SchDoc: DRIVERS (34S) - 60KW GM4 DAB CONTROL
size 431 x 279 mm; Date: 02/2025; DocumentNumber: CRD60DD12N-GMB-CONTROL; Revision: 2.0; SheetNumber: 6; SheetTotal: 12; SheetSize: B
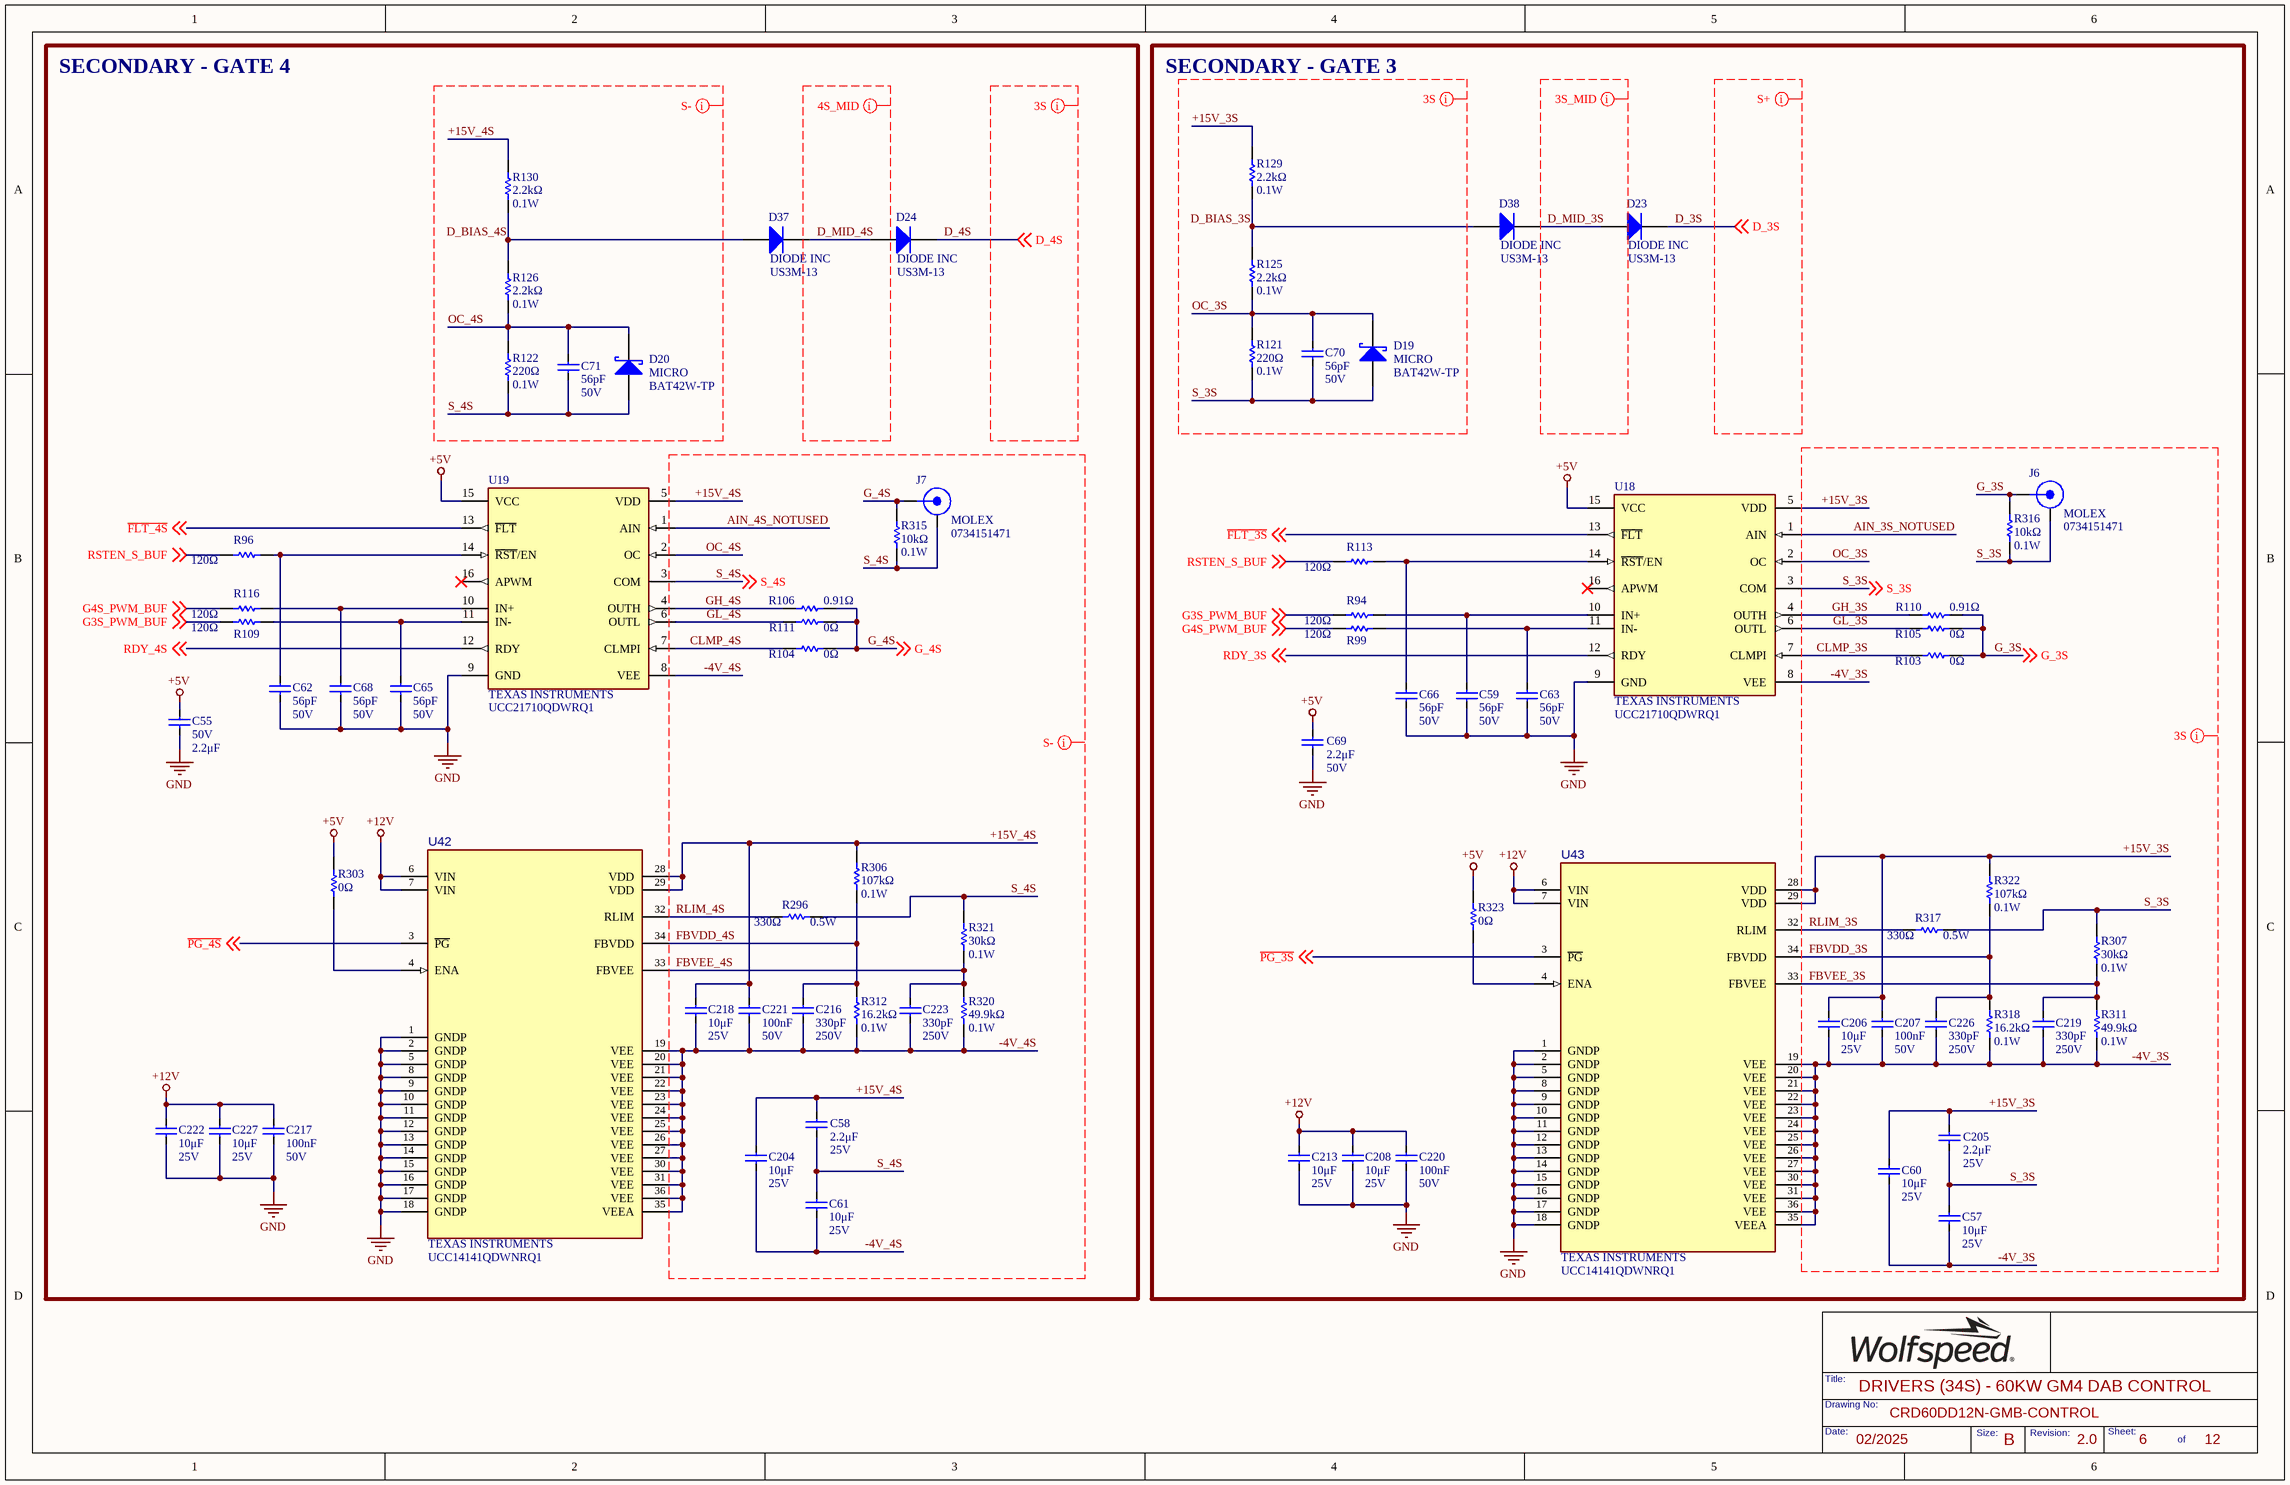
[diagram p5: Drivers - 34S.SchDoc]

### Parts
C55  Voltage Rating: 50V  Capacitance: 2.2μF  [FP-C0603C-CF-IPC_B]  (hidden comment: GRT188R61H225ME13D)
C57  value 10μF  Voltage Rating: 25V  [FP-CL31-IPC_C]  (hidden comment: CL31B106KAHSFNE)
C58  Voltage Rating: 25V  Capacitance: 2.2μF  [FP-CL31-IPC_C]  (hidden comment: 12063C225K4T2A)
C59  Capacitance: 56pF  Voltage Rating: 50V  [FP-C0603C-CF-IPC_B]  (hidden comment: CL10C560JB8NNNC)
C60  value 10μF  Voltage Rating: 25V  [FP-CL31-IPC_C]  (hidden comment: CL31B106KAHSFNE)
C61  value 10μF  Voltage Rating: 25V  [FP-CL31-IPC_C]  (hidden comment: CL31B106KAHSFNE)
C62  Capacitance: 56pF  Voltage Rating: 50V  [FP-C0603C-CF-IPC_B]  (hidden comment: CL10C560JB8NNNC)
C63  Capacitance: 56pF  Voltage Rating: 50V  [FP-C0603C-CF-IPC_B]  (hidden comment: CL10C560JB8NNNC)
C65  Capacitance: 56pF  Voltage Rating: 50V  [FP-C0603C-CF-IPC_B]  (hidden comment: CL10C560JB8NNNC)
C66  Capacitance: 56pF  Voltage Rating: 50V  [FP-C0603C-CF-IPC_B]  (hidden comment: CL10C560JB8NNNC)
C68  Capacitance: 56pF  Voltage Rating: 50V  [FP-C0603C-CF-IPC_B]  (hidden comment: CL10C560JB8NNNC)
C69  Voltage Rating: 50V  Capacitance: 2.2μF  [FP-C0603C-CF-IPC_B]  (hidden comment: GRT188R61H225ME13D)
C70  Capacitance: 56pF  Voltage Rating: 50V  [FP-C0603C-CF-IPC_B]  (hidden comment: CL10C560JB8NNNC)
C71  Capacitance: 56pF  Voltage Rating: 50V  [FP-C0603C-CF-IPC_B]  (hidden comment: CL10C560JB8NNNC)
C204  value 10μF  Voltage Rating: 25V  [FP-CL31-IPC_C]  (hidden comment: CL31B106KAHSFNE)
C205  Voltage Rating: 25V  Capacitance: 2.2μF  [FP-CL31-IPC_C]  (hidden comment: 12063C225K4T2A)
C206  value 10μF  Voltage Rating: 25V  [FP-CL31-IPC_C]  (hidden comment: CL31B106KAHSFNE)
C207  value 100nF  Voltage: 50V  [FP-C0603C-CF-IPC_B]  (hidden comment: CGA3E2X7R1H104K080AA)
C208  value 10μF  Voltage Rating: 25V  [FP-CL31-IPC_C]  (hidden comment: CL31B106KAHSFNE)
C213  value 10μF  Voltage Rating: 25V  [FP-CL31-IPC_C]  (hidden comment: CL31B106KAHSFNE)
C216  value 330pF  Voltage Rating: 250V  [FP-C0603C-CF-IPC_B]  (hidden comment: C0603C331JAGAC7867)
C217  value 100nF  Voltage: 50V  [FP-C0603C-CF-IPC_B]  (hidden comment: CGA3E2X7R1H104K080AA)
C218  value 10μF  Voltage Rating: 25V  [FP-CL31-IPC_C]  (hidden comment: CL31B106KAHSFNE)
C219  value 330pF  Voltage Rating: 250V  [FP-C0603C-CF-IPC_B]  (hidden comment: C0603C331JAGAC7867)
C220  value 100nF  Voltage: 50V  [FP-C0603C-CF-IPC_B]  (hidden comment: CGA3E2X7R1H104K080AA)
C221  value 100nF  Voltage: 50V  [FP-C0603C-CF-IPC_B]  (hidden comment: CGA3E2X7R1H104K080AA)
C222  value 10μF  Voltage Rating: 25V  [FP-CL31-IPC_C]  (hidden comment: CL31B106KAHSFNE)
C223  value 330pF  Voltage Rating: 250V  [FP-C0603C-CF-IPC_B]  (hidden comment: C0603C331JAGAC7867)
C226  value 330pF  Voltage Rating: 250V  [FP-C0603C-CF-IPC_B]  (hidden comment: C0603C331JAGAC7867)
C227  value 10μF  Voltage Rating: 25V  [FP-CL31-IPC_C]  (hidden comment: CL31B106KAHSFNE)
D19  Manufacturer: MICRO  [SOD3716X135N]  (hidden comment: BAT42W-TP)
D20  Manufacturer: MICRO  [SOD3716X135N]  (hidden comment: BAT42W-TP)
D23  Manufacturer: DIODE INC  [DIOM6959X25N]  (hidden comment: US3M-13)
D24  Manufacturer: DIODE INC  [DIOM6959X25N]  (hidden comment: US3M-13)
D37  Manufacturer: DIODE INC  [DIOM6959X25N]  (hidden comment: US3M-13)
D38  Manufacturer: DIODE INC  [DIOM6959X25N]  (hidden comment: US3M-13)
J6  0734151471  Manufacturer Print: MOLEX  [FP-73415-1471-MFG]
J7  0734151471  Manufacturer Print: MOLEX  [FP-73415-1471-MFG]
R94  value 120Ω  [FP-MCR03-IPC_B]  (hidden comment: RC0603JR-07120RL)
R96  value 120Ω  [FP-MCR03-IPC_B]  (hidden comment: RC0603JR-07120RL)
R99  value 120Ω  [FP-MCR03-IPC_B]  (hidden comment: RC0603JR-07120RL)
R103  Resistance: 0Ω  [FP-MCR03-IPC_B]  (hidden comment: CRCW06030000Z0EB)
R104  Resistance: 0Ω  [FP-MCR03-IPC_B]  (hidden comment: CRCW06030000Z0EB)
R105  value 0Ω  [RESC3125X70X40NL20T20]  (hidden comment: CRCW12100000Z0EAHP)
R106  value 0.91Ω  [RESC3125X70X40NL20T20]  (hidden comment: RCWE1210R910FKEA)
R109  value 120Ω  [FP-MCR03-IPC_B]  (hidden comment: RC0603JR-07120RL)
R110  value 0.91Ω  [RESC3125X70X40NL20T20]  (hidden comment: RCWE1210R910FKEA)
R111  value 0Ω  [RESC3125X70X40NL20T20]  (hidden comment: CRCW12100000Z0EAHP)
R113  value 120Ω  [FP-MCR03-IPC_B]  (hidden comment: RC0603JR-07120RL)
R116  value 120Ω  [FP-MCR03-IPC_B]  (hidden comment: RC0603JR-07120RL)
R121  Resistance: 220Ω  Power Rating: 0.1W  [FP-MCR03-IPC_B]  (hidden comment: RT0603FRE07220RL)
R122  Resistance: 220Ω  Power Rating: 0.1W  [FP-MCR03-IPC_B]  (hidden comment: RT0603FRE07220RL)
R125  value 2.2kΩ  Power: 0.1W  [FP-MCR03-IPC_B]  (hidden comment: RC0603FR-102K2L)
R126  value 2.2kΩ  Power: 0.1W  [FP-MCR03-IPC_B]  (hidden comment: RC0603FR-102K2L)
R129  value 2.2kΩ  Power: 0.1W  [FP-MCR03-IPC_B]  (hidden comment: RC0603FR-102K2L)
R130  value 2.2kΩ  Power: 0.1W  [FP-MCR03-IPC_B]  (hidden comment: RC0603FR-102K2L)
R296  value 330Ω  Power: 0.5W  [RESC3125X70X40NL20T20]  (hidden comment: RC1210JR-07330RL)
R303  Resistance: 0Ω  [FP-MCR03-IPC_B]  (hidden comment: CRCW06030000Z0EB)
R306  value 107kΩ  Power Rating: 0.1W  [FP-MCR03-IPC_B]  (hidden comment: RT0603BRD07107KL)
R307  value 30kΩ  Power Rating: 0.1W  [FP-MCR03-IPC_B]  (hidden comment: RT0603DRE0730KL)
R311  value 49.9kΩ  Power Rating: 0.1W  [FP-MCR03-IPC_B]  (hidden comment: RT0603FRE0749K9L)
R312  value 16.2kΩ  Power Rating: 0.1W  [FP-MCR03-IPC_B]  (hidden comment: RT0603BRD0716K2L)
R315  Resistance: 10kΩ  Max Power Dissipation: 0.1W  [FP-MCR03-IPC_B]  (hidden comment: ERJ3EKF1002V)
R316  Resistance: 10kΩ  Max Power Dissipation: 0.1W  [FP-MCR03-IPC_B]  (hidden comment: ERJ3EKF1002V)
R317  value 330Ω  Power: 0.5W  [RESC3125X70X40NL20T20]  (hidden comment: RC1210JR-07330RL)
R318  value 16.2kΩ  Power Rating: 0.1W  [FP-MCR03-IPC_B]  (hidden comment: RT0603BRD0716K2L)
R320  value 49.9kΩ  Power Rating: 0.1W  [FP-MCR03-IPC_B]  (hidden comment: RT0603FRE0749K9L)
R321  value 30kΩ  Power Rating: 0.1W  [FP-MCR03-IPC_B]  (hidden comment: RT0603DRE0730KL)
R322  value 107kΩ  Power Rating: 0.1W  [FP-MCR03-IPC_B]  (hidden comment: RT0603BRD07107KL)
R323  Resistance: 0Ω  [FP-MCR03-IPC_B]  (hidden comment: CRCW06030000Z0EB)
U18  UCC21710QDWRQ1  Manufacturer: TEXAS INSTRUMENTS  [FP-DW0016B-IPC_B]
U19  UCC21710QDWRQ1  Manufacturer: TEXAS INSTRUMENTS  [FP-DW0016B-IPC_B]
U42  Manufacturer: TEXAS INSTRUMENTS  [DWN0036-IPC-MFG]  (hidden comment: UCC14141QDWNRQ1)
U43  Manufacturer: TEXAS INSTRUMENTS  [DWN0036-IPC-MFG]  (hidden comment: UCC14141QDWNRQ1)

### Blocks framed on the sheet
SECONDARY - GATE 4: C55 C58 C61 C62 C65 C68 C71 C204 C216-C218 C221-C223 C227 D20 D24 D37 J7 R96 R104 R106 R109 R111 R116 R122 R126 R130 R296 R303 R306 R312 R315 R320 R321 U19 U42
SECONDARY - GATE 3: C57 C59 C60 C63 C66 C69 C70 C205-C208 C213 C219 C220 C226 D19 D23 D38 J6 R94 R99 R103 R105 R110 R113 R121 R125 R129 R307 R311 R316-R318 R322 R323 U18 U43

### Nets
+5V: C55.1 C69.1 R303.2 R323.2 U18.15(VCC) U19.15(VCC)
+12V: C208.1 C213.1 C217.1 C220.1 C222.1 C227.1 U42.6(VIN) U42.7(VIN) U43.6(VIN) U43.7(VIN)
GND: C55.2 C59.2 C62.2 C63.2 C65.2 C66.2 C68.2 C69.2 C208.2 C213.2 C217.2 C220.2 C222.2 C227.2 U18.9(GND) U19.9(GND) U42.1(GNDP) U42.2(GNDP) U42.5(GNDP) U42.8(GNDP) U42.9(GNDP) U42.10(GNDP) U42.11(GNDP) U42.12(GNDP) U42.13(GNDP) U42.14(GNDP) U42.15(GNDP) U42.16(GNDP) U42.17(GNDP) U42.18(GNDP) U43.1(GNDP) U43.2(GNDP) U43.5(GNDP) U43.8(GNDP) U43.9(GNDP) U43.10(GNDP) U43.11(GNDP) U43.12(GNDP) U43.13(GNDP) U43.14(GNDP) U43.15(GNDP) U43.16(GNDP) U43.17(GNDP) U43.18(GNDP)
+15V_3S: C60.1 C205.1 C206.1 C207.1 R129.2 R322.2 U18.5(VDD) U43.28(VDD) U43.29(VDD)
+15V_4S: C58.1 C204.1 C218.1 C221.1 R130.2 R306.2 U19.5(VDD) U42.28(VDD) U42.29(VDD)
-4V_3S: C57.2 C60.2 C206.2 C207.2 C219.2 C226.2 R311.1 R318.1 U18.8(VEE) U43.19(VEE) U43.20(VEE) U43.21(VEE) U43.22(VEE) U43.23(VEE) U43.24(VEE) U43.25(VEE) U43.26(VEE) U43.27(VEE) U43.30(VEE) U43.31(VEE) U43.35(VEEA) U43.36(VEE)
-4V_4S: C61.2 C204.2 C216.2 C218.2 C221.2 C223.2 R312.1 R320.1 U19.8(VEE) U42.19(VEE) U42.20(VEE) U42.21(VEE) U42.22(VEE) U42.23(VEE) U42.24(VEE) U42.25(VEE) U42.26(VEE) U42.27(VEE) U42.30(VEE) U42.31(VEE) U42.35(VEEA) U42.36(VEE)
AIN_3S_NOTUSED: U18.1(AIN)
AIN_4S_NOTUSED: U19.1(AIN)
CLMP_3S: R103.1 U18.7(CLMPI)
CLMP_4S: R104.1 U19.7(CLMPI)
D_3S: D23.1(K) ; off-sheet D_3S
D_4S: D24.1(K) ; off-sheet D_4S
D_BIAS_3S: D38.2(A) R125.2 R129.1
D_BIAS_4S: D37.2(A) R126.2 R130.1
D_MID_3S: D23.2(A) D38.1(K)
D_MID_4S: D24.2(A) D37.1(K)
~{FLT_3S}: U18.13(~{FLT}) ; off-sheet ~{FLT_3S}
~{FLT_4S}: U19.13(~{FLT}) ; off-sheet ~{FLT_4S}
FBVDD_3S: C226.1 R318.2 R322.1 U43.34(FBVDD)
FBVDD_4S: C216.1 R306.1 R312.2 U42.34(FBVDD)
FBVEE_3S: C219.1 R307.1 R311.2 U43.33(FBVEE)
FBVEE_4S: C223.1 R320.2 R321.1 U42.33(FBVEE)
G3S_PWM_BUF: R94.1 R109.1 ; off-sheet G3S_PWM_BUF
G4S_PWM_BUF: R99.1 R116.1 ; off-sheet G4S_PWM_BUF
G_3S: J6.1(CENTER) R103.2 R105.2 R110.2 R316.2 ; off-sheet G_3S
G_4S: J7.1(CENTER) R104.2 R106.2 R111.2 R315.2 ; off-sheet G_4S
GH_3S: R110.1 U18.4(OUTH)
GH_4S: R106.1 U19.4(OUTH)
GL_3S: R105.1 U18.6(OUTL)
GL_4S: R111.1 U19.6(OUTL)
OC_3S: C70.1 D19.1(K) R121.2 R125.1 U18.2(OC)
OC_4S: C71.1 D20.1(K) R122.2 R126.1 U19.2(OC)
~{PG_3S}: U43.3(~{PG}) ; off-sheet ~{PG_3S}
~{PG_4S}: U42.3(~{PG}) ; off-sheet ~{PG_4S}
RDY_3S: U18.12(RDY) ; off-sheet RDY_3S
RDY_4S: U19.12(RDY) ; off-sheet RDY_4S
RLIM_3S: R317.1 U43.32(RLIM)
RLIM_4S: R296.1 U42.32(RLIM)
RSTEN_S_BUF: R96.1 R113.1 ; off-sheet RSTEN_S_BUF
S_3S: C57.1 C70.2 C205.2 D19.2(A) J6.2,3,4,5(SHIELD) R121.1 R307.2 R316.1 R317.2 U18.3(COM) ; off-sheet S_3S
S_4S: C58.2 C61.1 C71.2 D20.2(A) J7.2,3,4,5(SHIELD) R122.1 R296.2 R315.1 R321.2 U19.3(COM) ; off-sheet S_4S
NetC59_1: C59.1 R94.2 U18.10(IN+)
NetC62_1: C62.1 R96.2 U19.14(~{RST}/EN)
NetC63_1: C63.1 R99.2 U18.11(IN-)
NetC65_1: C65.1 R109.2 U19.11(IN-)
NetC66_1: C66.1 R113.2 U18.14(~{RST}/EN)
NetC68_1: C68.1 R116.2 U19.10(IN+)
NetR303_1: R303.1 U42.4(ENA)
NetR323_1: R323.1 U43.4(ENA)

Not connected (* = marked no-connect by the designer): U18 16(APWM)*; U19 16(APWM)*

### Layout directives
net class S-_CLASS: +15V_4S, -4V_4S, AIN_4S_NOTUSED, CLMP_4S, D_BIAS_4S, FBVDD_4S, FBVEE_4S, G_4S, GH_4S, GL_4S, OC_4S, RLIM_4S, S_4S
net class 3S_CLASS: +15V_3S, -4V_3S, AIN_3S_NOTUSED, CLMP_3S, D_4S, D_BIAS_3S, FBVDD_3S, FBVEE_3S, G_3S, GH_3S, GL_3S, OC_3S, RLIM_3S, S_3S
net class 4SMID_CLASS: D_MID_4S
net class S+_CLASS: D_3S
net class 3SMID_CLASS: D_MID_3S

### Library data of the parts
C55 C69 = GRT188R61H225ME13D: as C7 on sheet Drivers - 34P
C57 C60 C61 C204 C206 C208 C213 C218 C222 C227 = CL31B106KAHSFNE: as C8 on sheet Drivers - 34P
C58 C205 = 12063C225K4T2A: as C9 on sheet Drivers - 34P
C59 C62 C63 C65 C66 C68 C70 C71 = CL10C560JB8NNNC: as C10 on sheet Drivers - 34P
C207 C217 C220 C221 = CGA3E2X7R1H104K080AA: as C96 on sheet Drivers - 34P
C216 C219 C223 C226 = C0603C331JAGAC7867: as C100 on sheet Drivers - 34P
D19 D20 = BAT42W-TP: DIODE SCHOTTKY 30V 200MA SOD123
D23 D24 D37 D38 = CMP-004-00052-3: DIODE GEN PURP 1KV 3A SMC
J6 J7 = 0734151471: as J2 on sheet Drivers - 34P
R94 R96 R99 R109 R113 R116 = RC0603JR-07120RL: as R16-R18 on sheet Drivers - 34P
R103 R104 R303 R323 = CRCW06030000Z0EB: as R19 on sheet Drivers - 34P
R105 R111 = CRCW12100000Z0EAHP: as R21 on sheet Drivers - 34P
R106 R110 = CMP-2005-02198-1: as R22 on sheet Drivers - 34P
R121 R122 = RT0603FRE07220RL: as R28 on sheet Drivers - 34P
R125 R126 R129 R130 = RC0603FR-102K2L: as R30-R33 on sheet Drivers - 34P
R296 R317 = RC1210JR-07330RL: as R166 on sheet Drivers - 34P
R306 R322 = RT0603BRD07107KL: as R174 on sheet Drivers - 34P
R307 R321 = RT0603DRE0730KL: as R175 on sheet Drivers - 34P
R311 R320 = RT0603FRE0749K9L: as R176 on sheet Drivers - 34P
R312 R318 = RT0603BRD0716K2L: as R177 on sheet Drivers - 34P
R315 R316 = ERJ3EKF1002V: as R178 on sheet Drivers - 34P
U18 U19 = CMP-00024-00019-13: DGTL ISO 5.7KV 1CH GT DVR 16SOIC
U42 U43 = UCC14141QDWNRQ1: as U28 on sheet Drivers - 34P

## Sheet Fault Logic - P.SchDoc: FAULT LOGIC (P) - 60KW GM4 DAB CONTROL
size 431 x 279 mm; Date: 02/2025; DocumentNumber: CRD60DD12N-GMB-CONTROL; Revision: 2.0; SheetNumber: 7; SheetTotal: 12; SheetSize: B
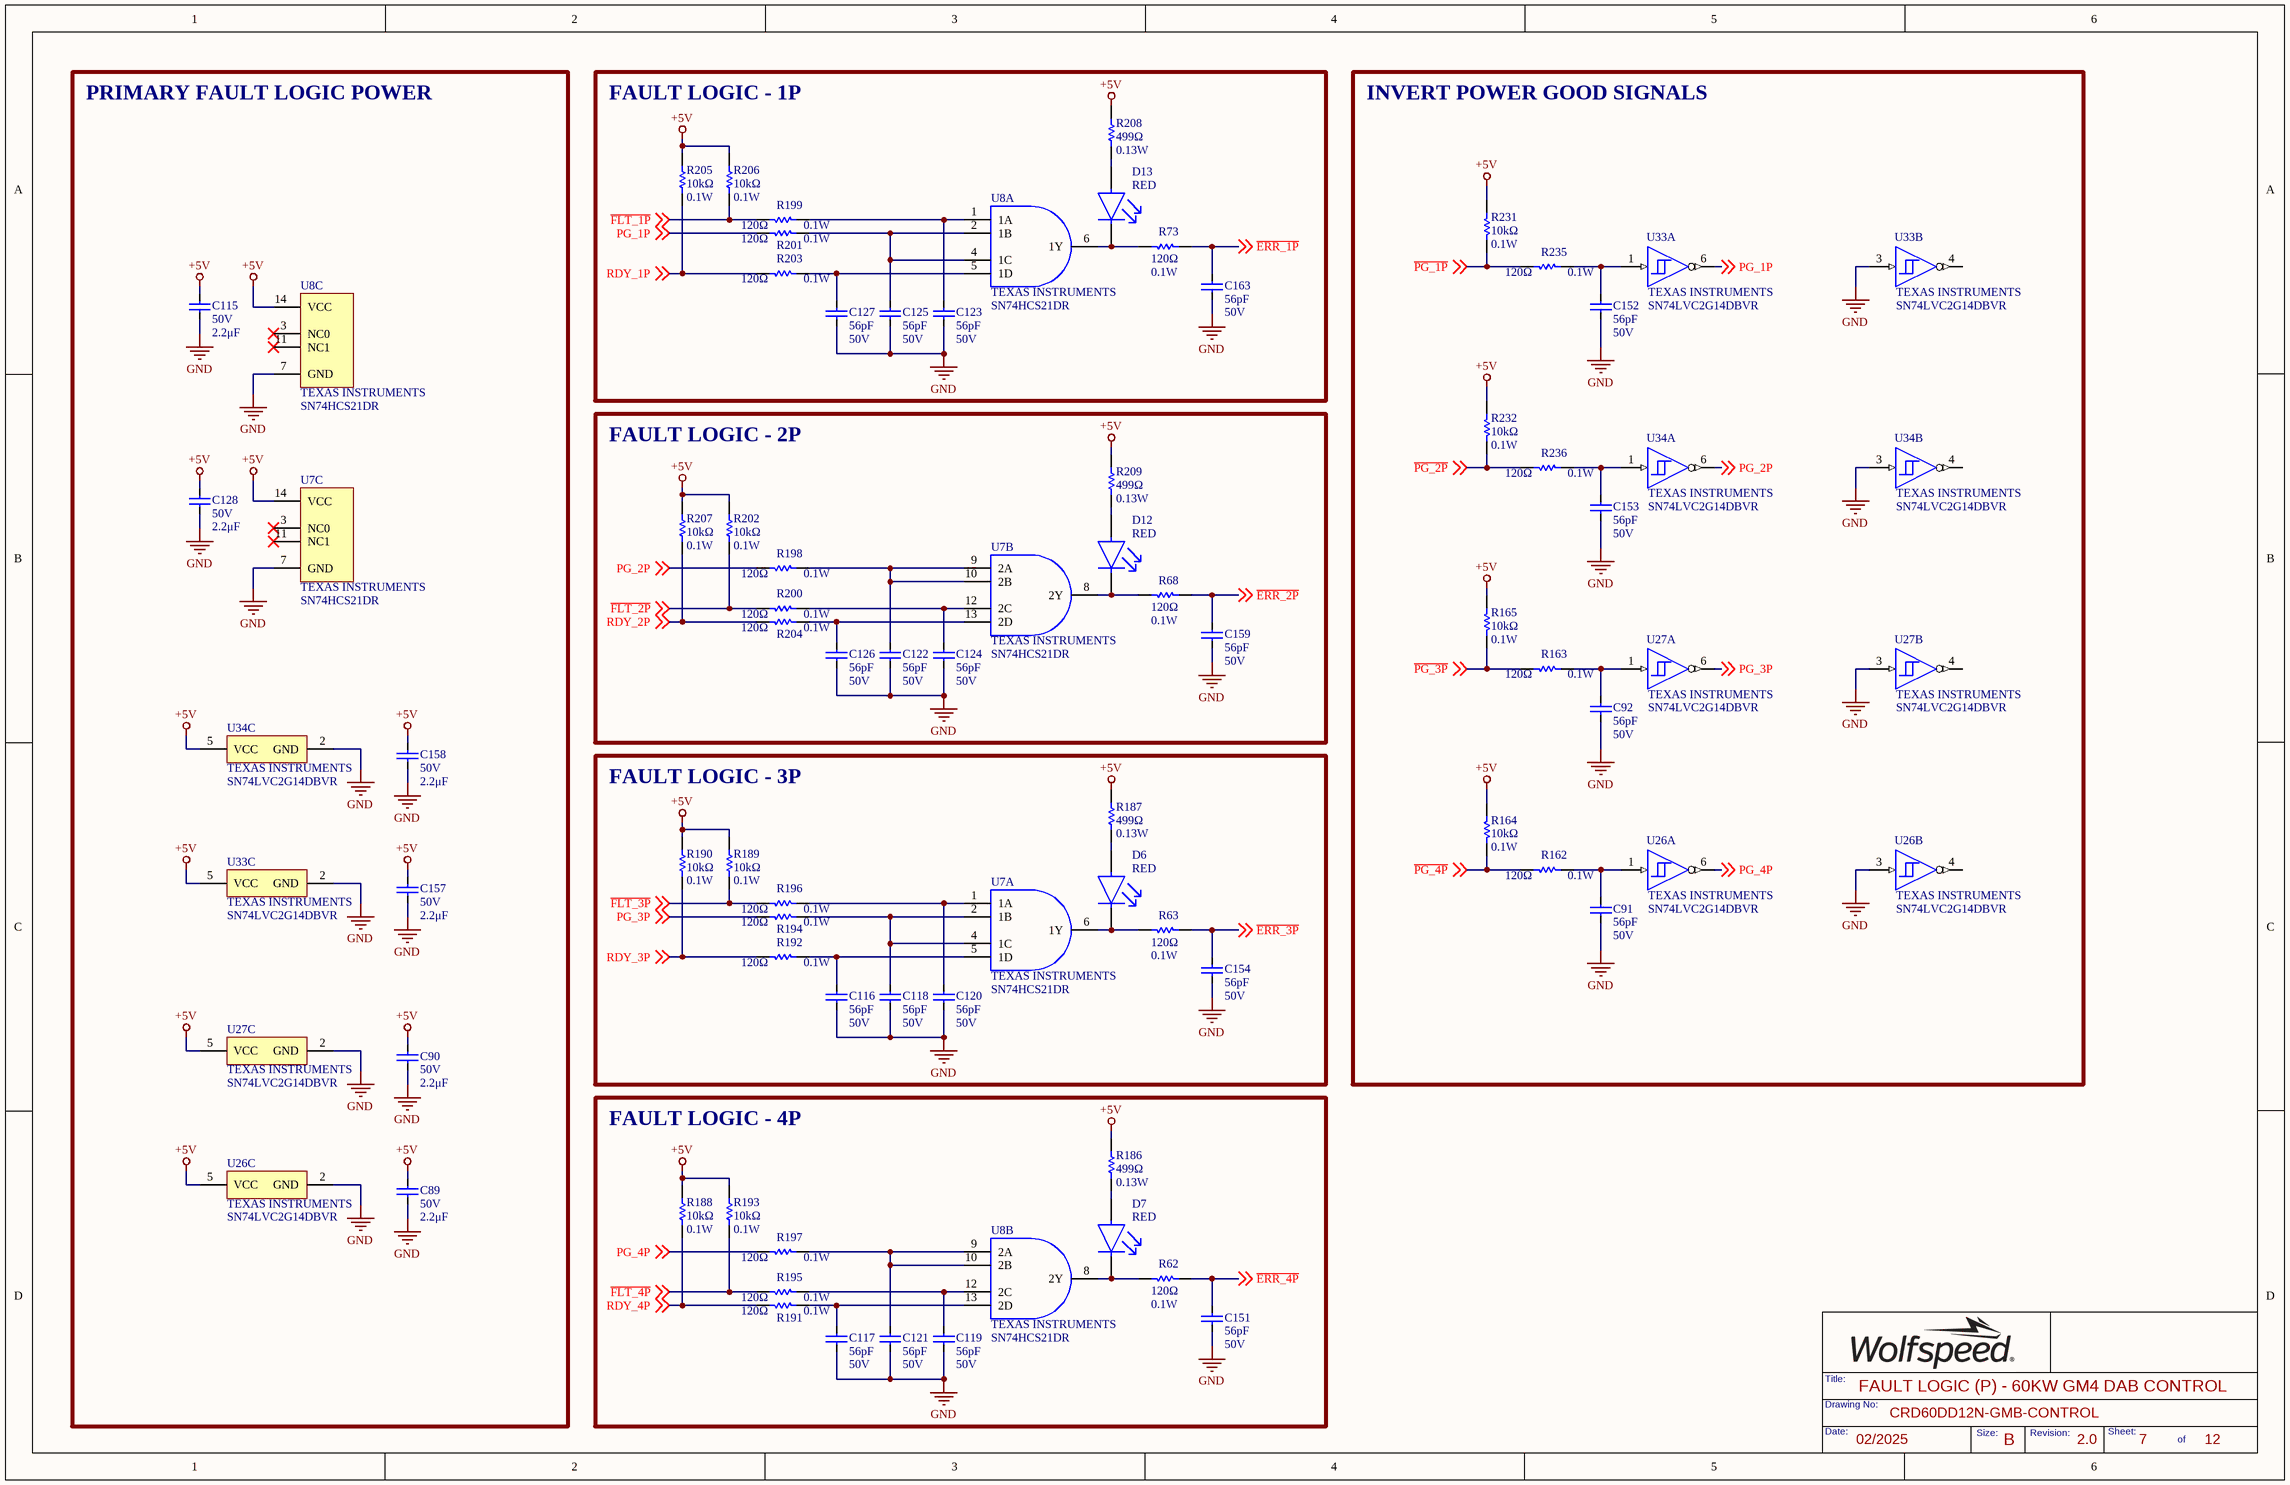
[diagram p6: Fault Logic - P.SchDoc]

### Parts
C89  Voltage Rating: 50V  Capacitance: 2.2μF  [FP-C0603C-CF-IPC_B]  (hidden comment: GRT188R61H225ME13D)
C90  Voltage Rating: 50V  Capacitance: 2.2μF  [FP-C0603C-CF-IPC_B]  (hidden comment: GRT188R61H225ME13D)
C91  Capacitance: 56pF  Voltage Rating: 50V  [FP-C0603C-CF-IPC_B]  (hidden comment: CL10C560JB8NNNC)
C92  Capacitance: 56pF  Voltage Rating: 50V  [FP-C0603C-CF-IPC_B]  (hidden comment: CL10C560JB8NNNC)
C115  Voltage Rating: 50V  Capacitance: 2.2μF  [FP-C0603C-CF-IPC_B]  (hidden comment: GRT188R61H225ME13D)
C116  Capacitance: 56pF  Voltage Rating: 50V  [FP-C0603C-CF-IPC_B]  (hidden comment: CL10C560JB8NNNC)
C117  Capacitance: 56pF  Voltage Rating: 50V  [FP-C0603C-CF-IPC_B]  (hidden comment: CL10C560JB8NNNC)
C118  Capacitance: 56pF  Voltage Rating: 50V  [FP-C0603C-CF-IPC_B]  (hidden comment: CL10C560JB8NNNC)
C119  Capacitance: 56pF  Voltage Rating: 50V  [FP-C0603C-CF-IPC_B]  (hidden comment: CL10C560JB8NNNC)
C120  Capacitance: 56pF  Voltage Rating: 50V  [FP-C0603C-CF-IPC_B]  (hidden comment: CL10C560JB8NNNC)
C121  Capacitance: 56pF  Voltage Rating: 50V  [FP-C0603C-CF-IPC_B]  (hidden comment: CL10C560JB8NNNC)
C122  Capacitance: 56pF  Voltage Rating: 50V  [FP-C0603C-CF-IPC_B]  (hidden comment: CL10C560JB8NNNC)
C123  Capacitance: 56pF  Voltage Rating: 50V  [FP-C0603C-CF-IPC_B]  (hidden comment: CL10C560JB8NNNC)
C124  Capacitance: 56pF  Voltage Rating: 50V  [FP-C0603C-CF-IPC_B]  (hidden comment: CL10C560JB8NNNC)
C125  Capacitance: 56pF  Voltage Rating: 50V  [FP-C0603C-CF-IPC_B]  (hidden comment: CL10C560JB8NNNC)
C126  Capacitance: 56pF  Voltage Rating: 50V  [FP-C0603C-CF-IPC_B]  (hidden comment: CL10C560JB8NNNC)
C127  Capacitance: 56pF  Voltage Rating: 50V  [FP-C0603C-CF-IPC_B]  (hidden comment: CL10C560JB8NNNC)
C128  Voltage Rating: 50V  Capacitance: 2.2μF  [FP-C0603C-CF-IPC_B]  (hidden comment: GRT188R61H225ME13D)
C151  Capacitance: 56pF  Voltage Rating: 50V  [FP-C0603C-CF-IPC_B]  (hidden comment: CL10C560JB8NNNC)
C152  Capacitance: 56pF  Voltage Rating: 50V  [FP-C0603C-CF-IPC_B]  (hidden comment: CL10C560JB8NNNC)
C153  Capacitance: 56pF  Voltage Rating: 50V  [FP-C0603C-CF-IPC_B]  (hidden comment: CL10C560JB8NNNC)
C154  Capacitance: 56pF  Voltage Rating: 50V  [FP-C0603C-CF-IPC_B]  (hidden comment: CL10C560JB8NNNC)
C157  Voltage Rating: 50V  Capacitance: 2.2μF  [FP-C0603C-CF-IPC_B]  (hidden comment: GRT188R61H225ME13D)
C158  Voltage Rating: 50V  Capacitance: 2.2μF  [FP-C0603C-CF-IPC_B]  (hidden comment: GRT188R61H225ME13D)
C159  Capacitance: 56pF  Voltage Rating: 50V  [FP-C0603C-CF-IPC_B]  (hidden comment: CL10C560JB8NNNC)
C163  Capacitance: 56pF  Voltage Rating: 50V  [FP-C0603C-CF-IPC_B]  (hidden comment: CL10C560JB8NNNC)
D6  value RED  [FP-LTST-C171GKT-MFG-RED]  (hidden comment: HSMC-C170)
D7  value RED  [FP-LTST-C171GKT-MFG-RED]  (hidden comment: HSMC-C170)
D12  value RED  [FP-LTST-C171GKT-MFG-RED]  (hidden comment: HSMC-C170)
D13  value RED  [FP-LTST-C171GKT-MFG-RED]  (hidden comment: HSMC-C170)
R62  value 120Ω  Max Power Dissipation: 0.1W  [FP-MCR03-IPC_B]  (hidden comment: RC0603JR-07120RL)
R63  value 120Ω  Max Power Dissipation: 0.1W  [FP-MCR03-IPC_B]  (hidden comment: RC0603JR-07120RL)
R68  value 120Ω  Max Power Dissipation: 0.1W  [FP-MCR03-IPC_B]  (hidden comment: RC0603JR-07120RL)
R73  value 120Ω  Max Power Dissipation: 0.1W  [FP-MCR03-IPC_B]  (hidden comment: RC0603JR-07120RL)
R162  value 120Ω  Max Power Dissipation: 0.1W  [FP-MCR03-IPC_B]  (hidden comment: RC0603JR-07120RL)
R163  value 120Ω  Max Power Dissipation: 0.1W  [FP-MCR03-IPC_B]  (hidden comment: RC0603JR-07120RL)
R164  value 10kΩ  Max Power Dissipation: 0.1W  [FP-MCR03-IPC_B]  (hidden comment: ERJ3EKF1002V)
R165  value 10kΩ  Max Power Dissipation: 0.1W  [FP-MCR03-IPC_B]  (hidden comment: ERJ3EKF1002V)
R186  Resistance: 499Ω  Max Power Dissipation: 0.13W  [FP-MCR10-IPC_A]  (hidden comment: RC0805FR-07499RL)
R187  Resistance: 499Ω  Max Power Dissipation: 0.13W  [FP-MCR10-IPC_A]  (hidden comment: RC0805FR-07499RL)
R188  value 10kΩ  Max Power Dissipation: 0.1W  [FP-MCR03-IPC_B]  (hidden comment: ERJ3EKF1002V)
R189  value 10kΩ  Max Power Dissipation: 0.1W  [FP-MCR03-IPC_B]  (hidden comment: ERJ3EKF1002V)
R190  value 10kΩ  Max Power Dissipation: 0.1W  [FP-MCR03-IPC_B]  (hidden comment: ERJ3EKF1002V)
R191  value 120Ω  Max Power Dissipation: 0.1W  [FP-MCR03-IPC_B]  (hidden comment: RC0603JR-07120RL)
R192  value 120Ω  Max Power Dissipation: 0.1W  [FP-MCR03-IPC_B]  (hidden comment: RC0603JR-07120RL)
R193  value 10kΩ  Max Power Dissipation: 0.1W  [FP-MCR03-IPC_B]  (hidden comment: ERJ3EKF1002V)
R194  value 120Ω  Max Power Dissipation: 0.1W  [FP-MCR03-IPC_B]  (hidden comment: RC0603JR-07120RL)
R195  value 120Ω  Max Power Dissipation: 0.1W  [FP-MCR03-IPC_B]  (hidden comment: RC0603JR-07120RL)
R196  value 120Ω  Max Power Dissipation: 0.1W  [FP-MCR03-IPC_B]  (hidden comment: RC0603JR-07120RL)
R197  value 120Ω  Max Power Dissipation: 0.1W  [FP-MCR03-IPC_B]  (hidden comment: RC0603JR-07120RL)
R198  value 120Ω  Max Power Dissipation: 0.1W  [FP-MCR03-IPC_B]  (hidden comment: RC0603JR-07120RL)
R199  value 120Ω  Max Power Dissipation: 0.1W  [FP-MCR03-IPC_B]  (hidden comment: RC0603JR-07120RL)
R200  value 120Ω  Max Power Dissipation: 0.1W  [FP-MCR03-IPC_B]  (hidden comment: RC0603JR-07120RL)
R201  value 120Ω  Max Power Dissipation: 0.1W  [FP-MCR03-IPC_B]  (hidden comment: RC0603JR-07120RL)
R202  value 10kΩ  Max Power Dissipation: 0.1W  [FP-MCR03-IPC_B]  (hidden comment: ERJ3EKF1002V)
R203  value 120Ω  Max Power Dissipation: 0.1W  [FP-MCR03-IPC_B]  (hidden comment: RC0603JR-07120RL)
R204  value 120Ω  Max Power Dissipation: 0.1W  [FP-MCR03-IPC_B]  (hidden comment: RC0603JR-07120RL)
R205  value 10kΩ  Max Power Dissipation: 0.1W  [FP-MCR03-IPC_B]  (hidden comment: ERJ3EKF1002V)
R206  value 10kΩ  Max Power Dissipation: 0.1W  [FP-MCR03-IPC_B]  (hidden comment: ERJ3EKF1002V)
R207  value 10kΩ  Max Power Dissipation: 0.1W  [FP-MCR03-IPC_B]  (hidden comment: ERJ3EKF1002V)
R208  Resistance: 499Ω  Max Power Dissipation: 0.13W  [FP-MCR10-IPC_A]  (hidden comment: RC0805FR-07499RL)
R209  Resistance: 499Ω  Max Power Dissipation: 0.13W  [FP-MCR10-IPC_A]  (hidden comment: RC0805FR-07499RL)
R231  value 10kΩ  Max Power Dissipation: 0.1W  [FP-MCR03-IPC_B]  (hidden comment: ERJ3EKF1002V)
R232  value 10kΩ  Max Power Dissipation: 0.1W  [FP-MCR03-IPC_B]  (hidden comment: ERJ3EKF1002V)
R235  value 120Ω  Max Power Dissipation: 0.1W  [FP-MCR03-IPC_B]  (hidden comment: RC0603JR-07120RL)
R236  value 120Ω  Max Power Dissipation: 0.1W  [FP-MCR03-IPC_B]  (hidden comment: RC0603JR-07120RL)
U7  Manufacturer: TEXAS INSTRUMENTS  [SOIC_S21DR_TEX]  (hidden comment: SN74HCS21DR)  (parts A,B,C of 3)
U8  Manufacturer: TEXAS INSTRUMENTS  [SOIC_S21DR_TEX]  (hidden comment: SN74HCS21DR)  (parts A,B,C of 3)
U26  Manufacturer: TEXAS INSTRUMENTS  [DBV0006A_M]  (hidden comment: SN74LVC2G14DBVR)  (parts A,B,C of 3)
U27  Manufacturer: TEXAS INSTRUMENTS  [DBV0006A_M]  (hidden comment: SN74LVC2G14DBVR)  (parts A,B,C of 3)
U33  Manufacturer: TEXAS INSTRUMENTS  [DBV0006A_M]  (hidden comment: SN74LVC2G14DBVR)  (parts A,B,C of 3)
U34  Manufacturer: TEXAS INSTRUMENTS  [DBV0006A_M]  (hidden comment: SN74LVC2G14DBVR)  (parts A,B,C of 3)

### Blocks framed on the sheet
PRIMARY FAULT LOGIC POWER: C89 C90 C115 C128 C157 C158 U7 U8 U26 U27 U33 U34
FAULT LOGIC - 1P: C123 C125 C127 C163 D13 R73 R199 R201 R203 R205 R206 R208 U8
INVERT POWER GOOD SIGNALS: C91 C92 C152 C153 R162-R165 R231 R232 R235 R236 U26 U27 U33 U34
FAULT LOGIC - 2P: C122 C124 C126 C159 D12 R68 R198 R200 R202 R204 R207 R209 U7
FAULT LOGIC - 3P: C116 C118 C120 C154 D6 R63 R187 R189 R190 R192 R194 R196 U7
FAULT LOGIC - 4P: C117 C119 C121 C151 D7 R62 R186 R188 R191 R193 R195 R197 U8

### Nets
+5V: C89.1 C90.1 C115.1 C128.1 C157.1 C158.1 R164.1 R165.1 R186.2 R187.2 R188.2 R189.2 R190.2 R193.2 R202.2 R205.2 R206.2 R207.2 R208.2 R209.2 R231.1 R232.1 U7.14(VCC) U8.14(VCC) U26.5(VCC) U27.5(VCC) U33.5(VCC) U34.5(VCC)
GND: C89.2 C90.2 C91.2 C92.2 C115.2 C116.2 C117.2 C118.2 C119.2 C120.2 C121.2 C122.2 C123.2 C124.2 C125.2 C126.2 C127.2 C128.2 C151.2 C152.2 C153.2 C154.2 C157.2 C158.2 C159.2 C163.2 U7.7(GND) U8.7(GND) U26.2(GND) U26.3(2A) U27.2(GND) U27.3(2A) U33.2(GND) U33.3(2A) U34.2(GND) U34.3(2A)
~{ERR_1P}: C163.1 R73.1 ; off-sheet ~{ERR_1P}
~{ERR_2P}: C159.1 R68.1 ; off-sheet ~{ERR_2P}
~{ERR_3P}: C154.1 R63.1 ; off-sheet ~{ERR_3P}
~{ERR_4P}: C151.1 R62.1 ; off-sheet ~{ERR_4P}
~{FLT_1P}: R199.2 R206.1 ; off-sheet ~{FLT_1P}
~{FLT_2P}: R200.2 R202.1 ; off-sheet ~{FLT_2P}
~{FLT_3P}: R189.1 R196.2 ; off-sheet ~{FLT_3P}
~{FLT_4P}: R193.1 R195.2 ; off-sheet ~{FLT_4P}
~{PG_1P}: R231.2 R235.2 ; off-sheet ~{PG_1P}
~{PG_2P}: R232.2 R236.2 ; off-sheet ~{PG_2P}
~{PG_3P}: R163.2 R165.2 ; off-sheet ~{PG_3P}
~{PG_4P}: R162.2 R164.2 ; off-sheet ~{PG_4P}
PG_1P: R201.2 U33.6(1Y) ; off-sheet PG_1P
PG_2P: R198.2 U34.6(1Y) ; off-sheet PG_2P
PG_3P: R194.2 U27.6(1Y) ; off-sheet PG_3P
PG_4P: R197.2 U26.6(1Y) ; off-sheet PG_4P
RDY_1P: R203.2 R205.1 ; off-sheet RDY_1P
RDY_2P: R204.2 R207.1 ; off-sheet RDY_2P
RDY_3P: R190.1 R192.2 ; off-sheet RDY_3P
RDY_4P: R188.1 R191.2 ; off-sheet RDY_4P
NetC91_1: C91.1 R162.1 U26.1(1A)
NetC92_1: C92.1 R163.1 U27.1(1A)
NetC116_1: C116.1 R192.1 U7.5(1D)
NetC117_1: C117.1 R191.1 U8.13(2D)
NetC118_1: C118.1 R194.1 U7.2(1B) U7.4(1C)
NetC119_1: C119.1 R195.1 U8.12(2C)
NetC120_1: C120.1 R196.1 U7.1(1A)
NetC121_1: C121.1 R197.1 U8.9(2A) U8.10(2B)
NetC122_1: C122.1 R198.1 U7.9(2A) U7.10(2B)
NetC123_1: C123.1 R199.1 U8.1(1A)
NetC124_1: C124.1 R200.1 U7.12(2C)
NetC125_1: C125.1 R201.1 U8.2(1B) U8.4(1C)
NetC126_1: C126.1 R204.1 U7.13(2D)
NetC127_1: C127.1 R203.1 U8.5(1D)
NetC152_1: C152.1 R235.1 U33.1(1A)
NetC153_1: C153.1 R236.1 U34.1(1A)
NetD6_1: D6.1(C) R63.2 U7.6(1Y)
NetD6_2: D6.2(A) R187.1
NetD7_1: D7.1(C) R62.2 U8.8(2Y)
NetD7_2: D7.2(A) R186.1
NetD12_1: D12.1(C) R68.2 U7.8(2Y)
NetD12_2: D12.2(A) R209.1
NetD13_1: D13.1(C) R73.2 U8.6(1Y)
NetD13_2: D13.2(A) R208.1

Not connected (* = marked no-connect by the designer): U7 3(NC0)* 11(NC1)*; U8 3(NC0)* 11(NC1)*; U26 4(2Y); U27 4(2Y); U33 4(2Y); U34 4(2Y)

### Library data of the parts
C89 C90 C115 C128 C157 C158 = GRT188R61H225ME13D: as C7 on sheet Drivers - 34P
C91 C92 C116-C127 C151-C154 C159 C163 = CL10C560JB8NNNC: as C10 on sheet Drivers - 34P
D6 D7 D12 D13 = HSMC-C170: LED RED DIFFUSED CHIP SMD; Manufacturer: BROADCOM
R62 R63 R68 R73 R162 R163 R191 R192 R194-R201 R203 R204 R235 R236 = RC0603JR-07120RL: as R16-R18 on sheet Drivers - 34P
R164 R165 R188-R190 R193 R202 R205-R207 R231 R232 = ERJ3EKF1002V: RES SMD 10K OHM 1% 1/10W 0603; Manufacturer: PANASONIC; Manufacturer Part Number: ERJ-3EKF1002V; Temperature Coefficient: 100ppm/°C; Power Rating: 100mW; Voltage Rating: 75V
R186 R187 R208 R209 = RC0805FR-07499RL: RES 499 OHM 1% 1/8W 0805; Manufacturer: YAGEO; Power Rating: 125mW; Voltage Rating: 150V; Temperature Coefficient: 100ppm/°C; Value: 499Ω
U7 U8 = SN74HCS21DR: IC GATE AND 2CH 4-INP 14SOIC
U26 U27 U33 U34 = CMP-0859-00232-4: IC INVERTER 2CH 2-INP SOT23-6; ICC @ Nom Voltage(Max)(mA): 0.01; Input Type: CMOS/TTL; Logic: Inverting; Output Drive (IOL/IOH)(Max)(mA): 32/-32; VCC(Min)(V): 1.65; VCC(Max)(V): 5.5; Rating: Catalog; Technology Family: LVC; Sub-Family: Inverting Buffer/Driver; 3-State Output: No; Schmitt Trigger: Yes; Output Type: CMOS; tpd @ Nom Voltage(Max)(ns): 9.5,5.7,5.4,4.3; Voltage(Nom)(V): 1.8,2.5,3.3,5; F @ Nom Voltage(Max)(Mhz): 150; Bits(#): 2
